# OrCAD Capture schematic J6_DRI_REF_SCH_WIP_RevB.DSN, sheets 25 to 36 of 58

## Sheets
25 SH28 - DDR3 BANK1 CAPS: size B; rev: A
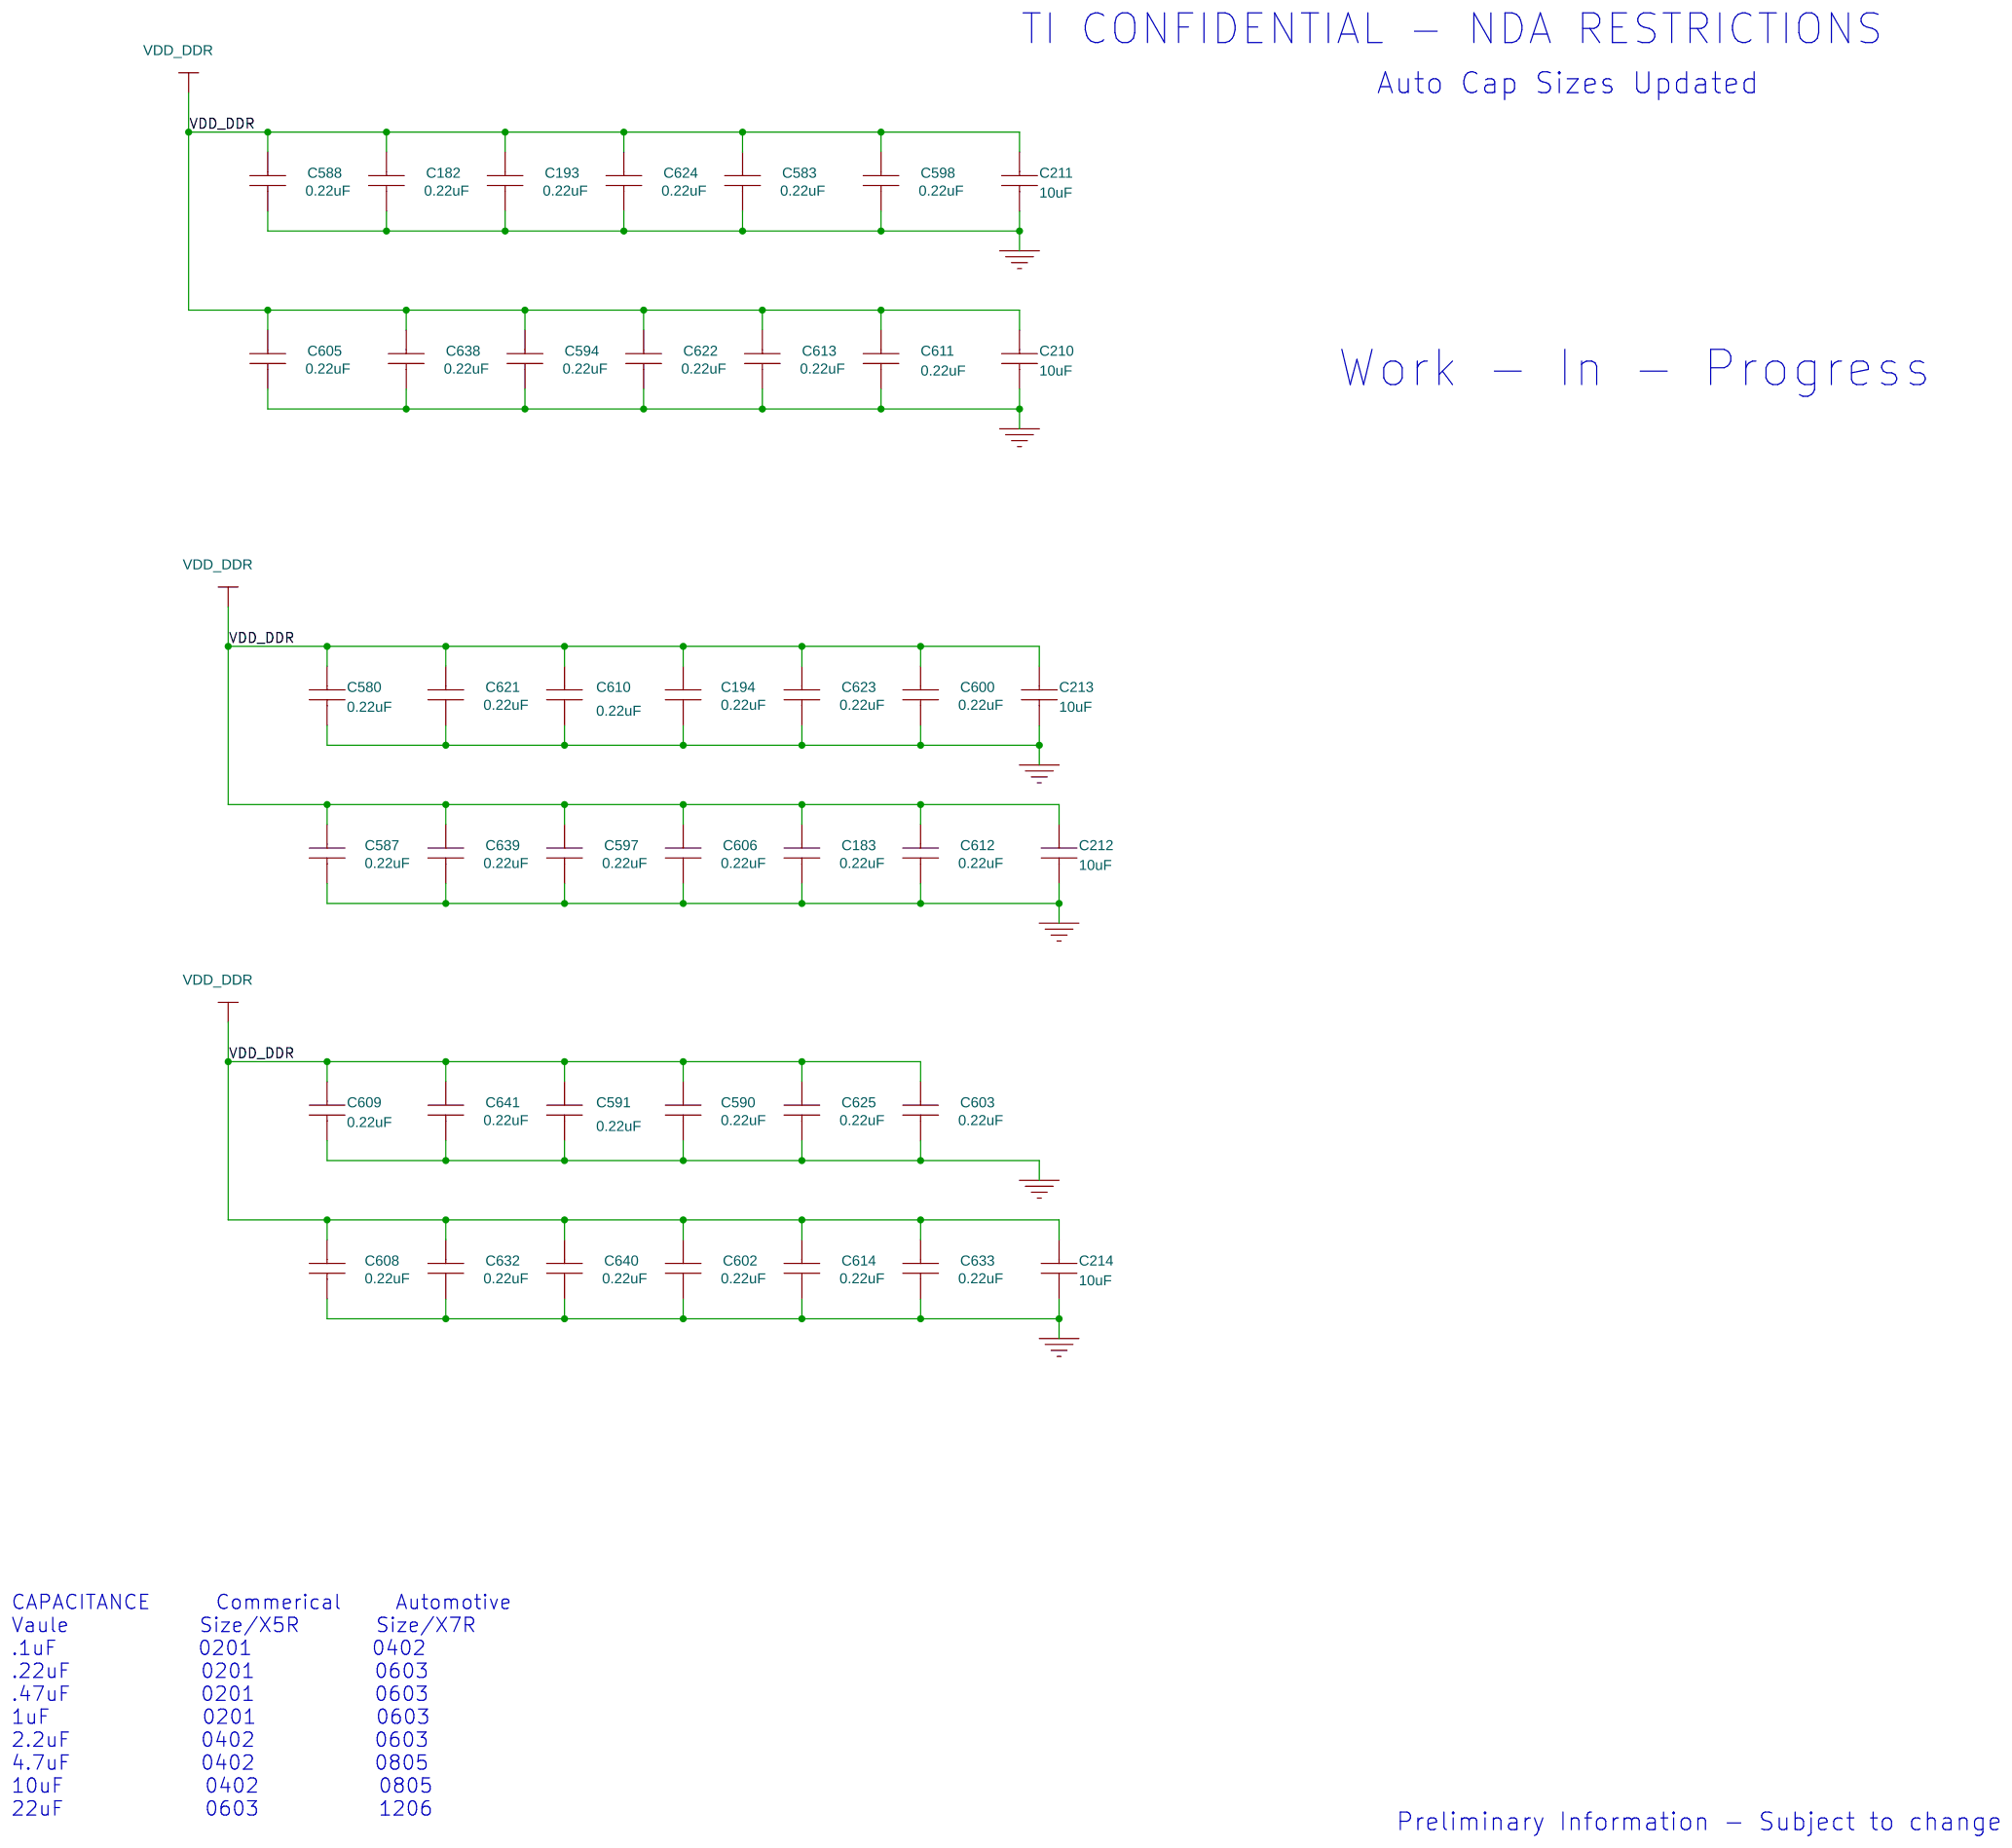
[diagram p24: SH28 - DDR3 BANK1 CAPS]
26 SH29 - DDR3 EMIF1 TERM: size B; rev: A
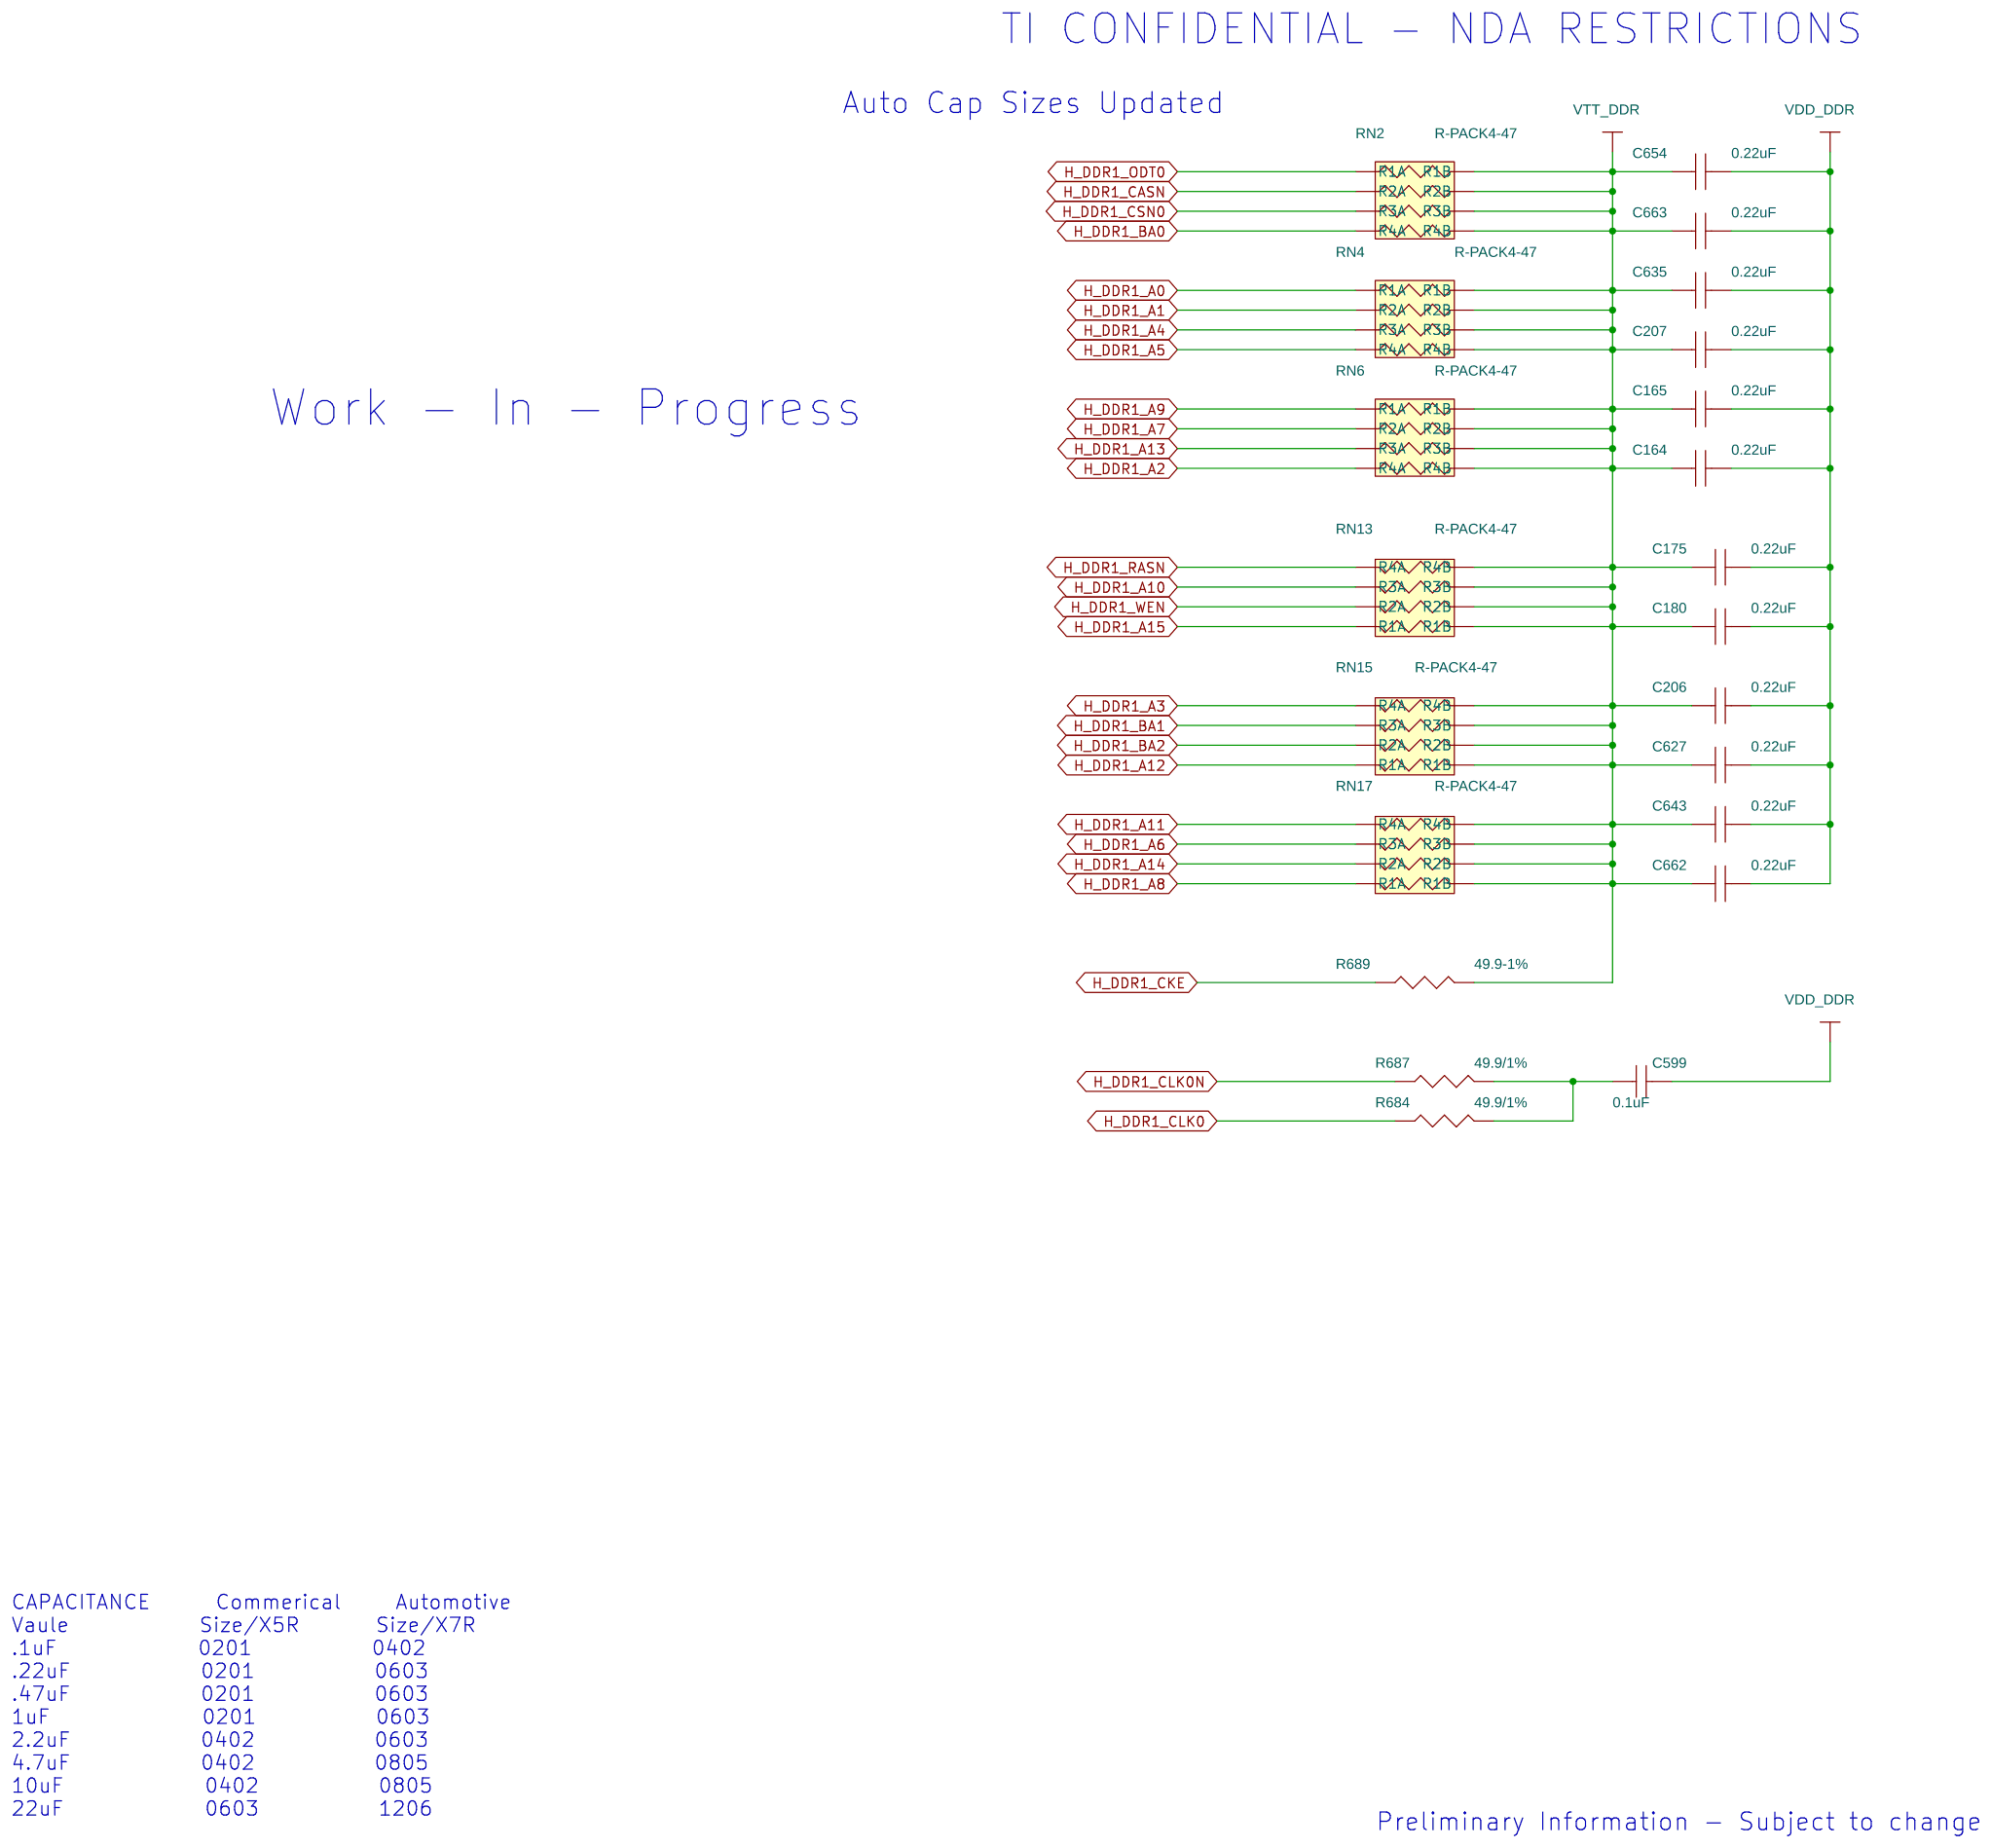
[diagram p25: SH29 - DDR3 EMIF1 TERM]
27 SH30 - DDR3 EMIF2 TESTPOINTS: size B; rev: A
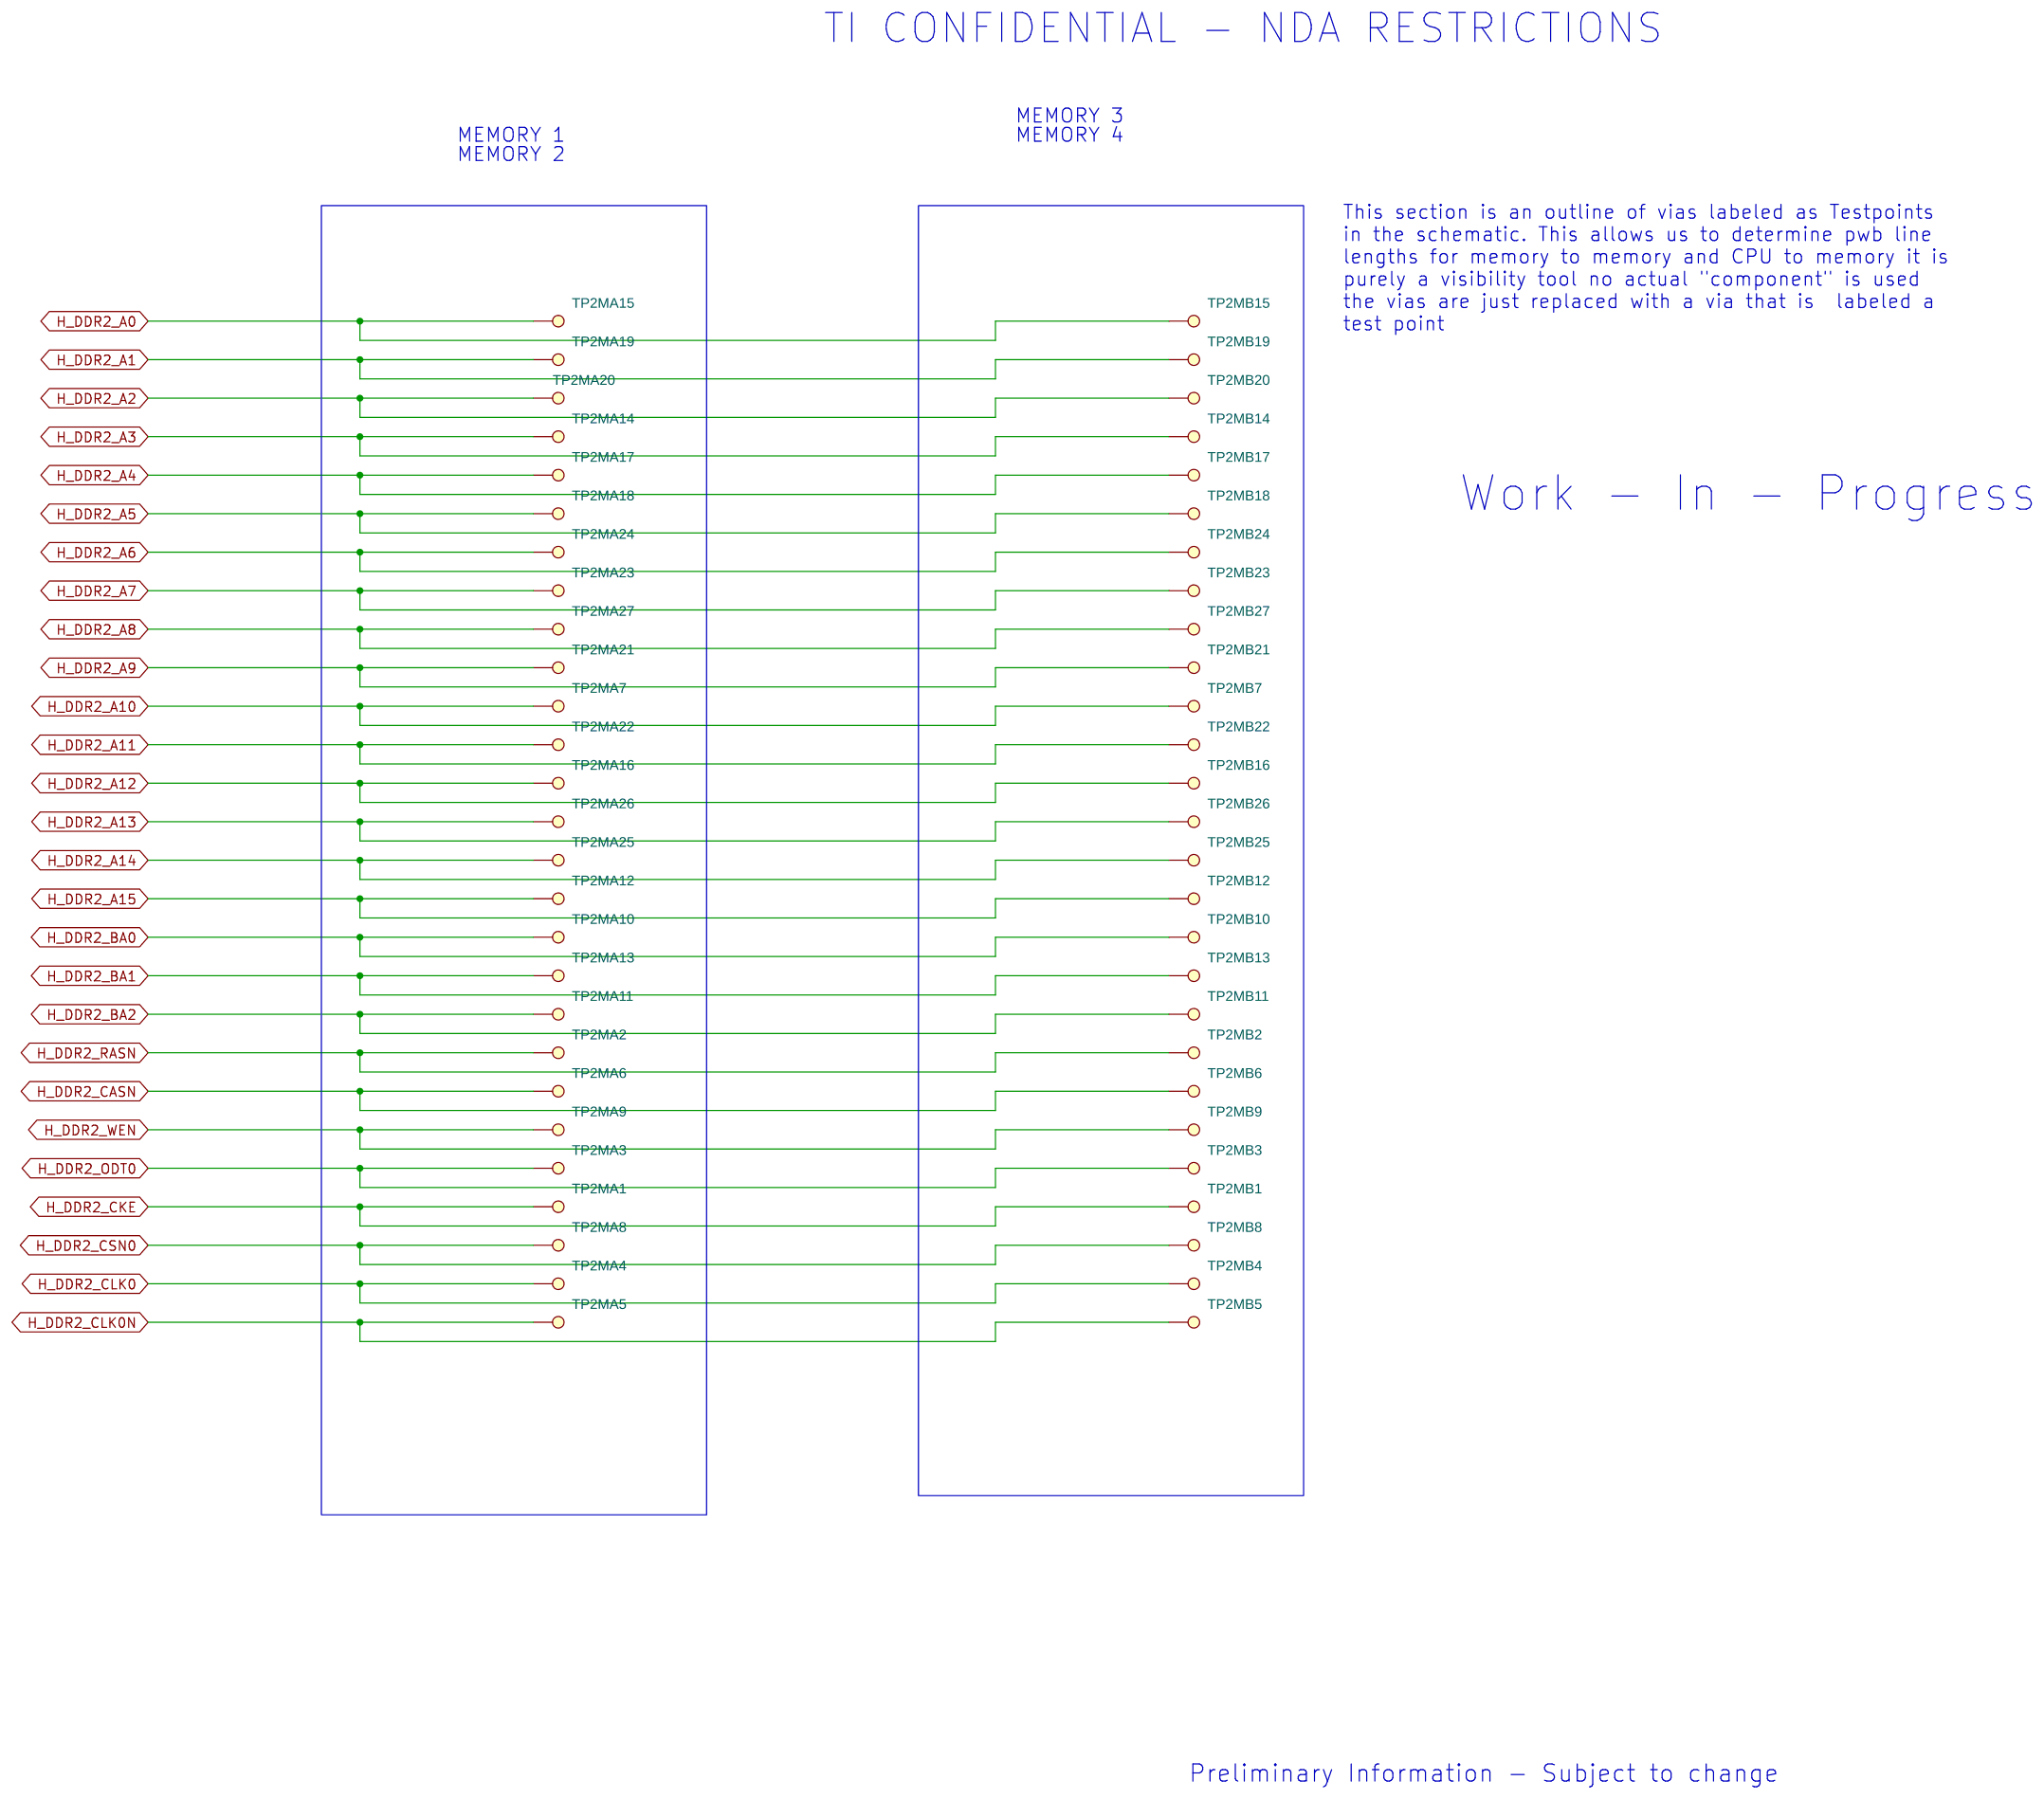
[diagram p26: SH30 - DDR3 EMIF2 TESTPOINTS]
28 SH31 - DDR3 EMIF2 BANK 2: size B; rev: A
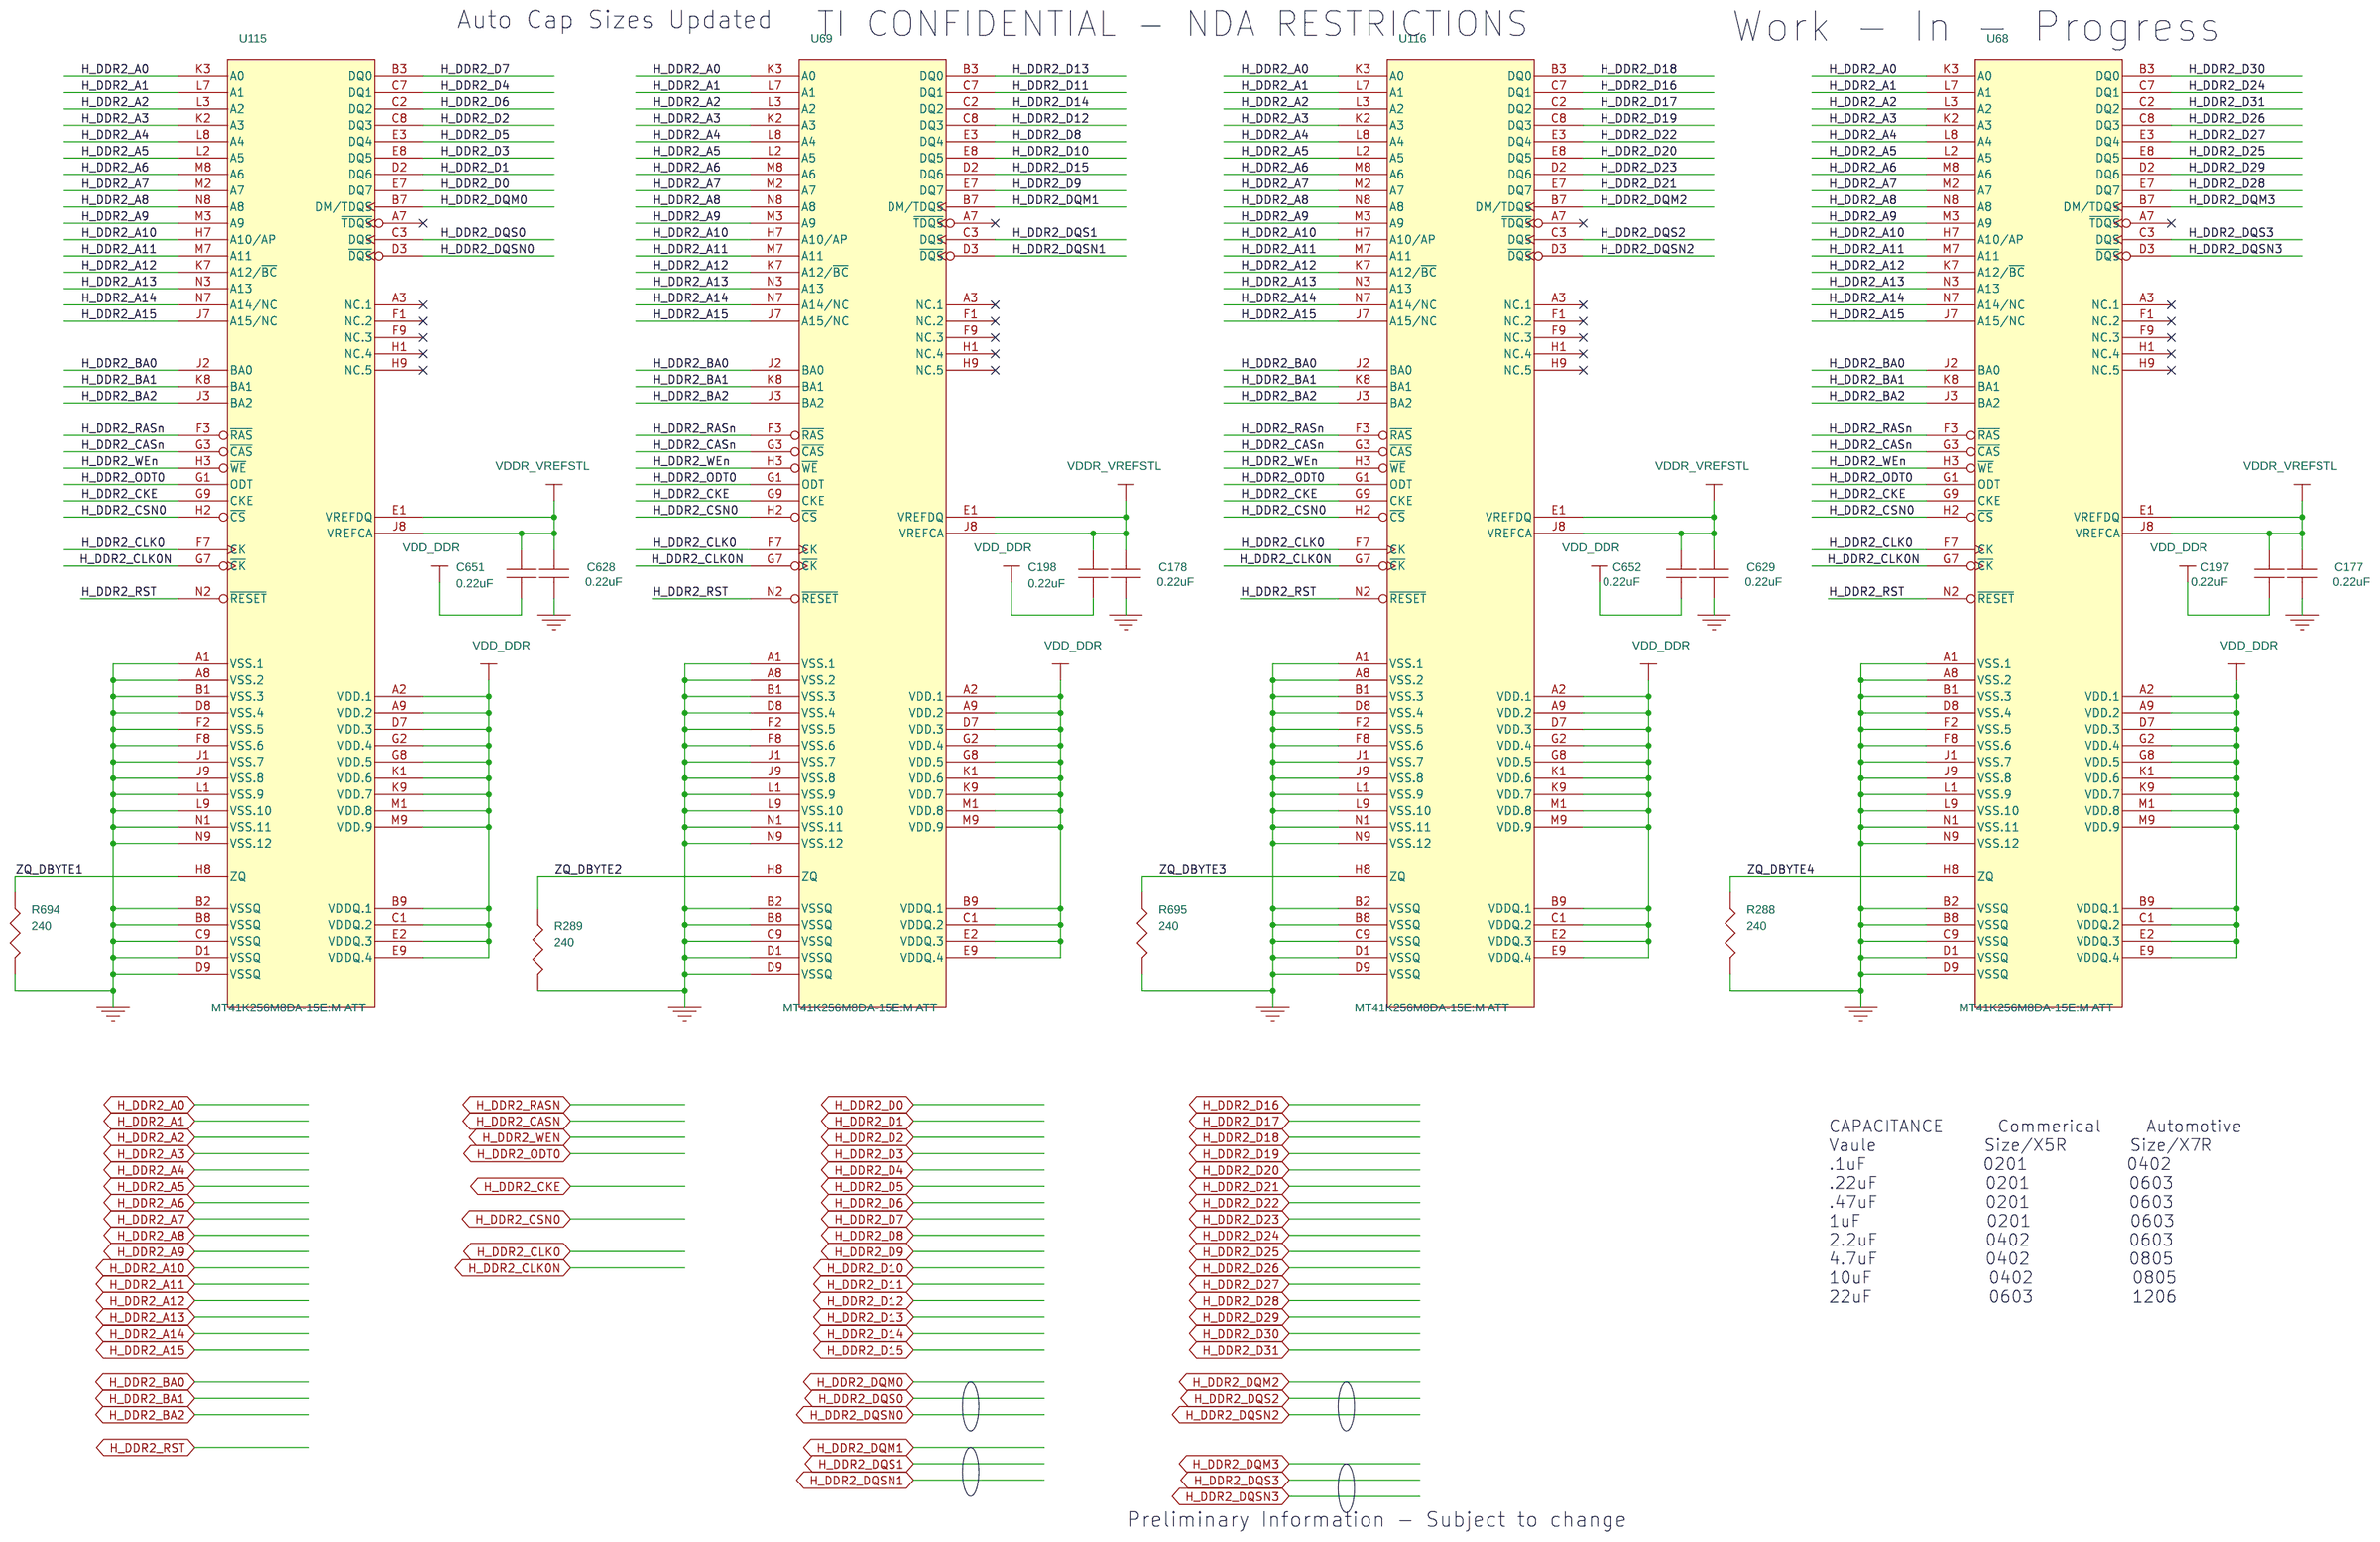
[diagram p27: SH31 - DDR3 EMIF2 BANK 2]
29 SH32 - DDR3 BANK2 CAPS: size B; rev: A
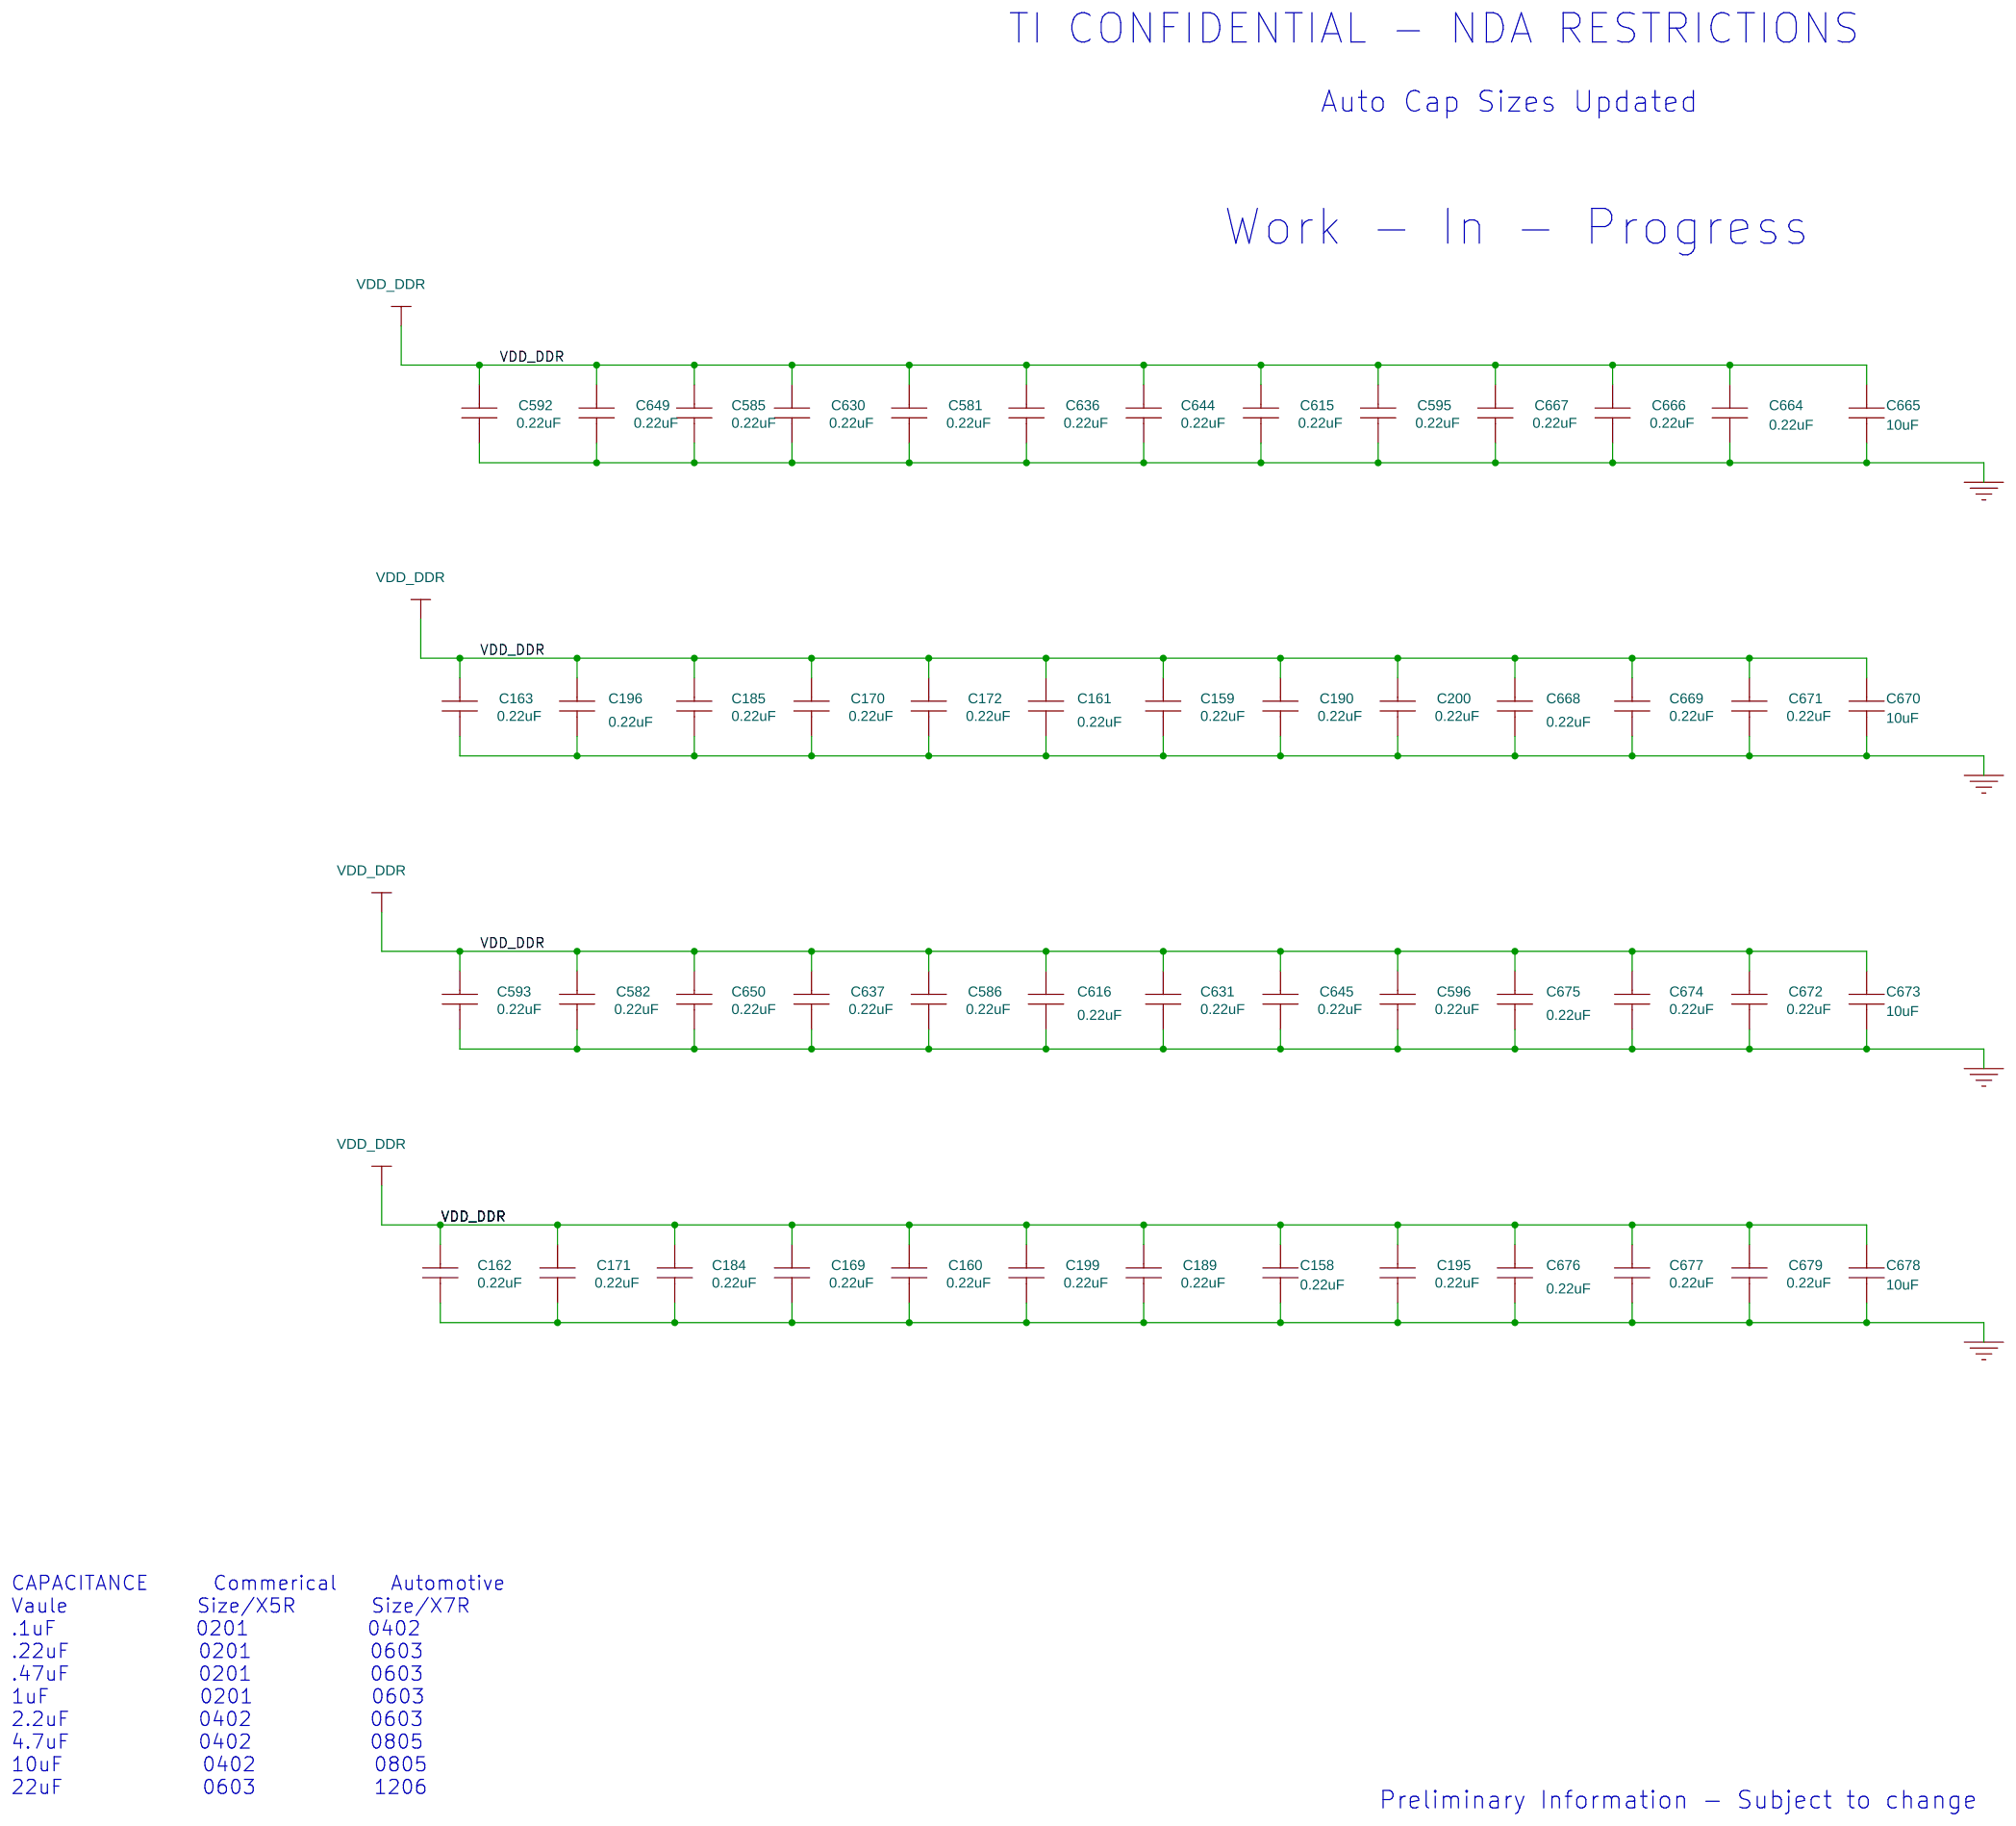
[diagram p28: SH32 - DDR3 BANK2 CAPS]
30 SH33 - DDR3 EMIF2 TERM: size B; rev: A
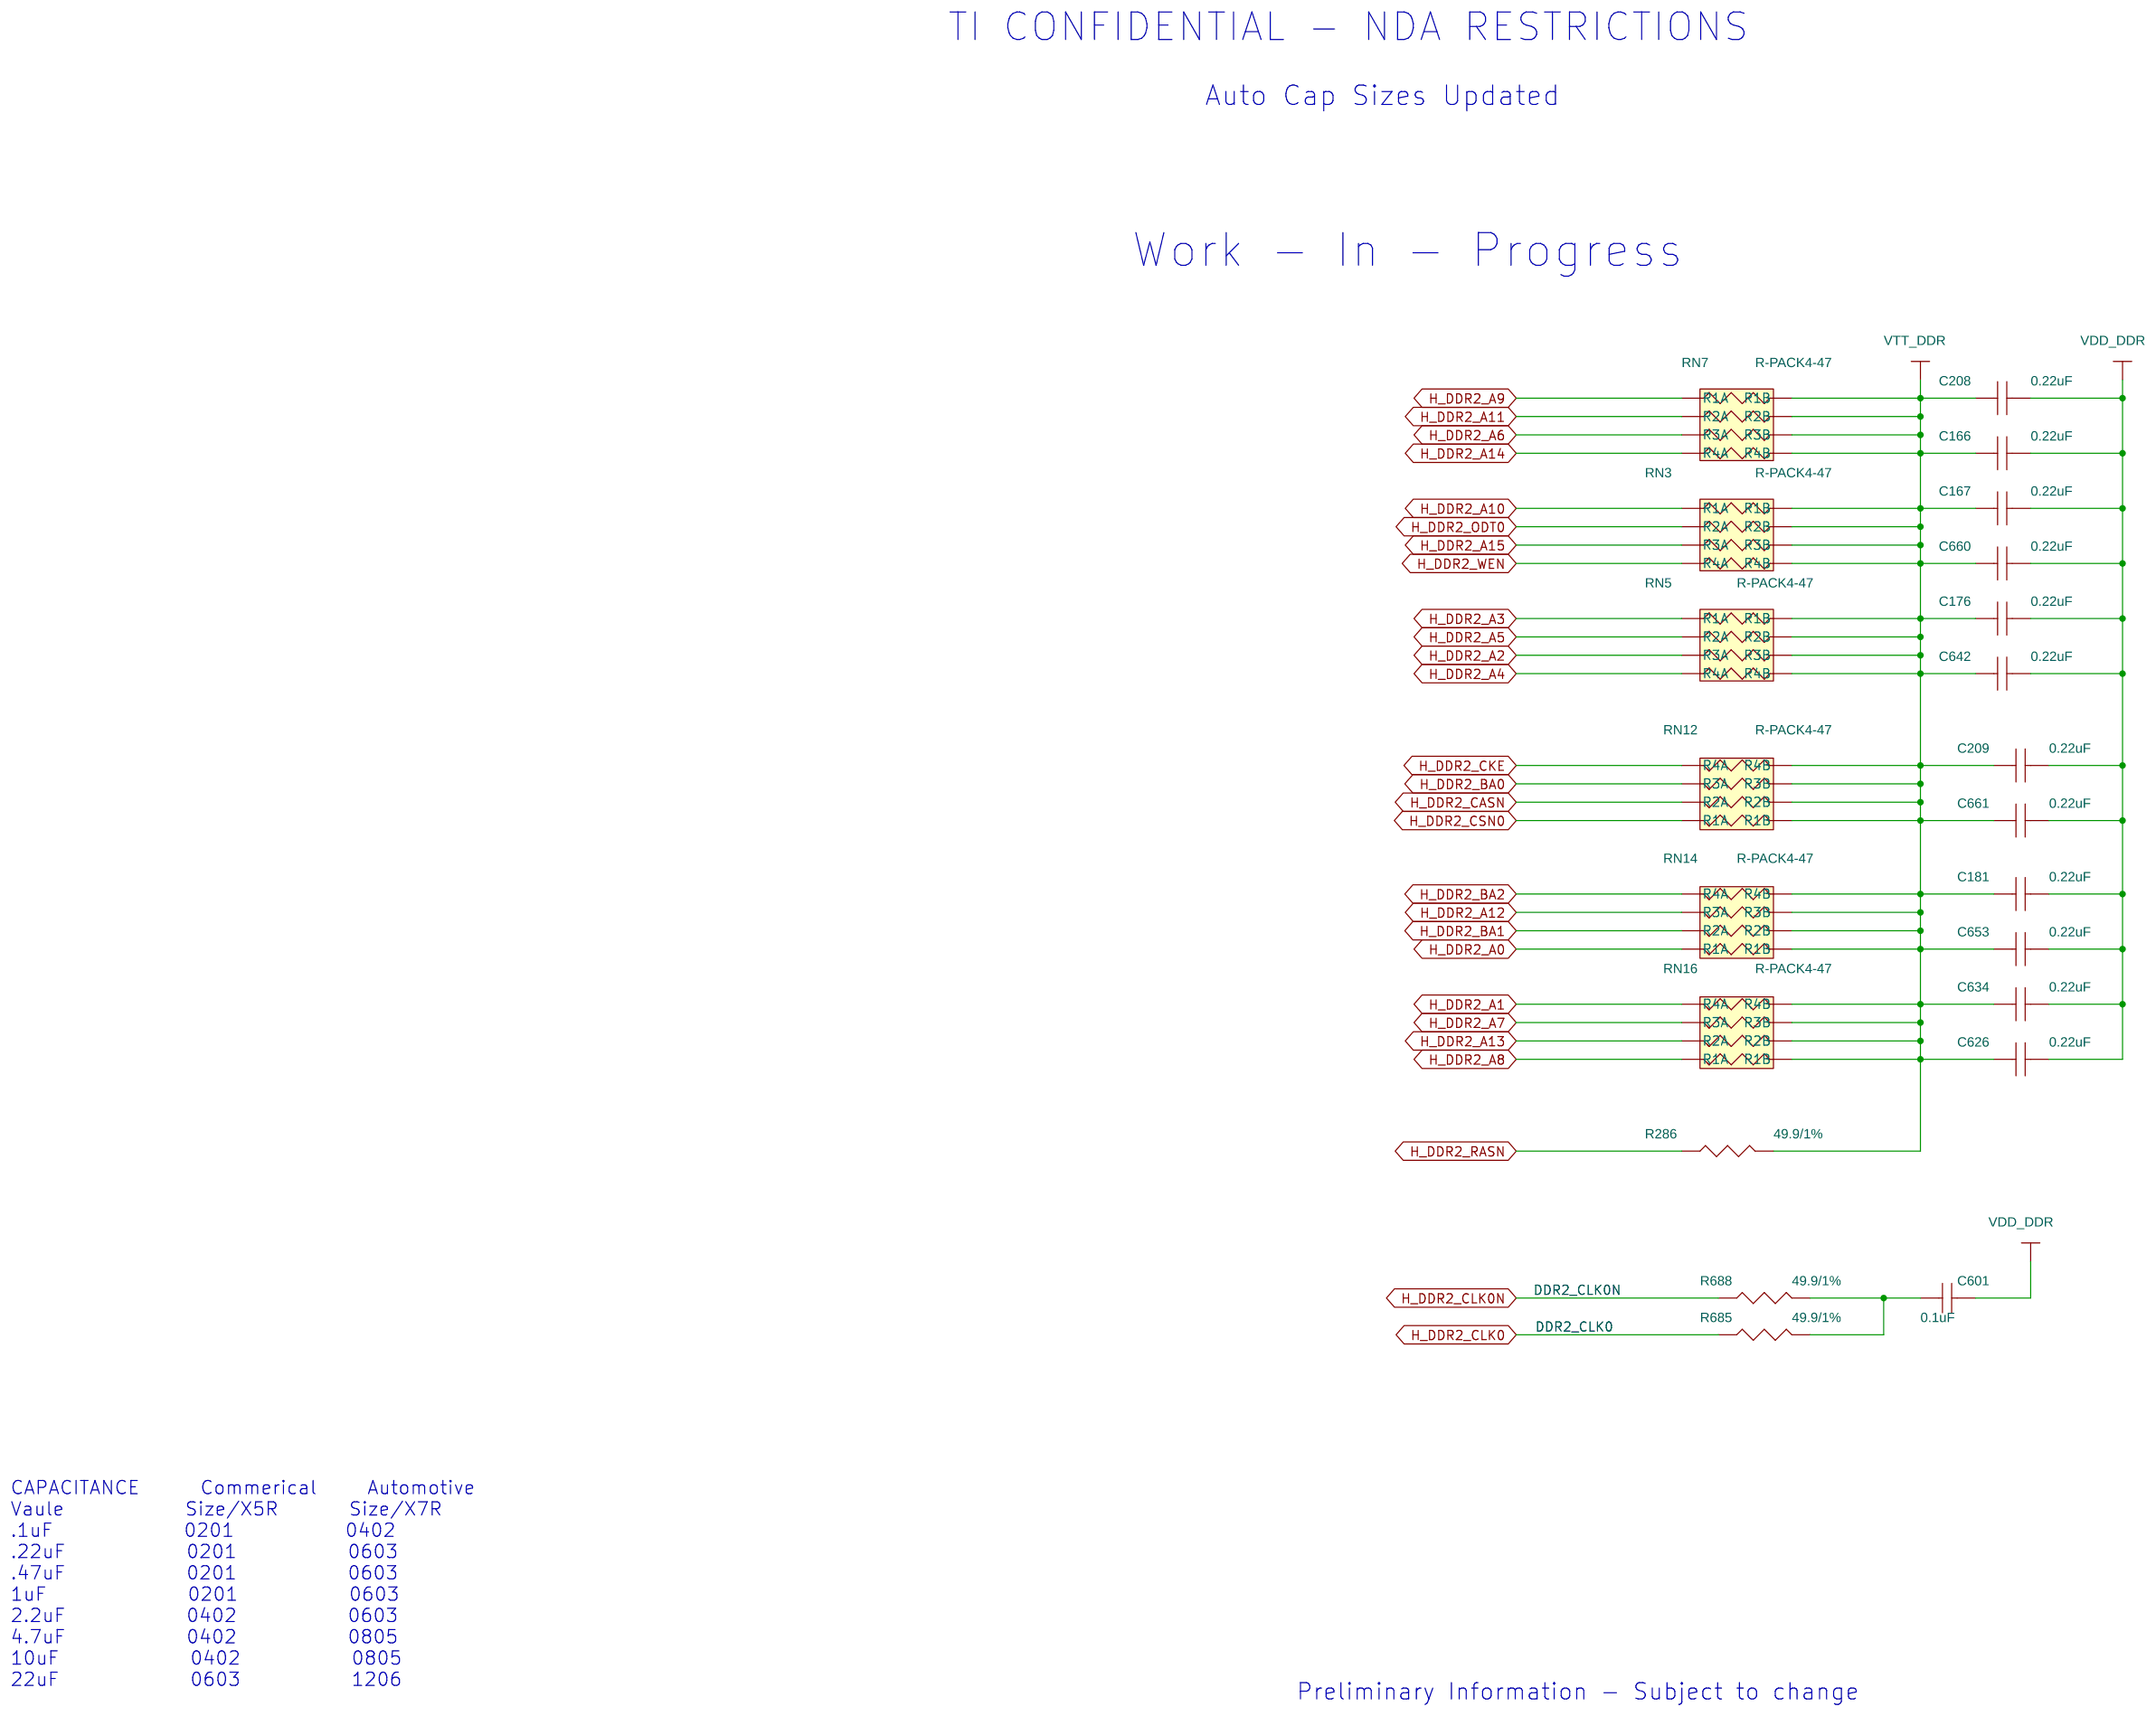
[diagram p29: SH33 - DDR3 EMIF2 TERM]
31 SH33 - HDMI OUTPUT CONNECTOR: size B; title: VAYU EVM; rev: E; note: 516582-0001
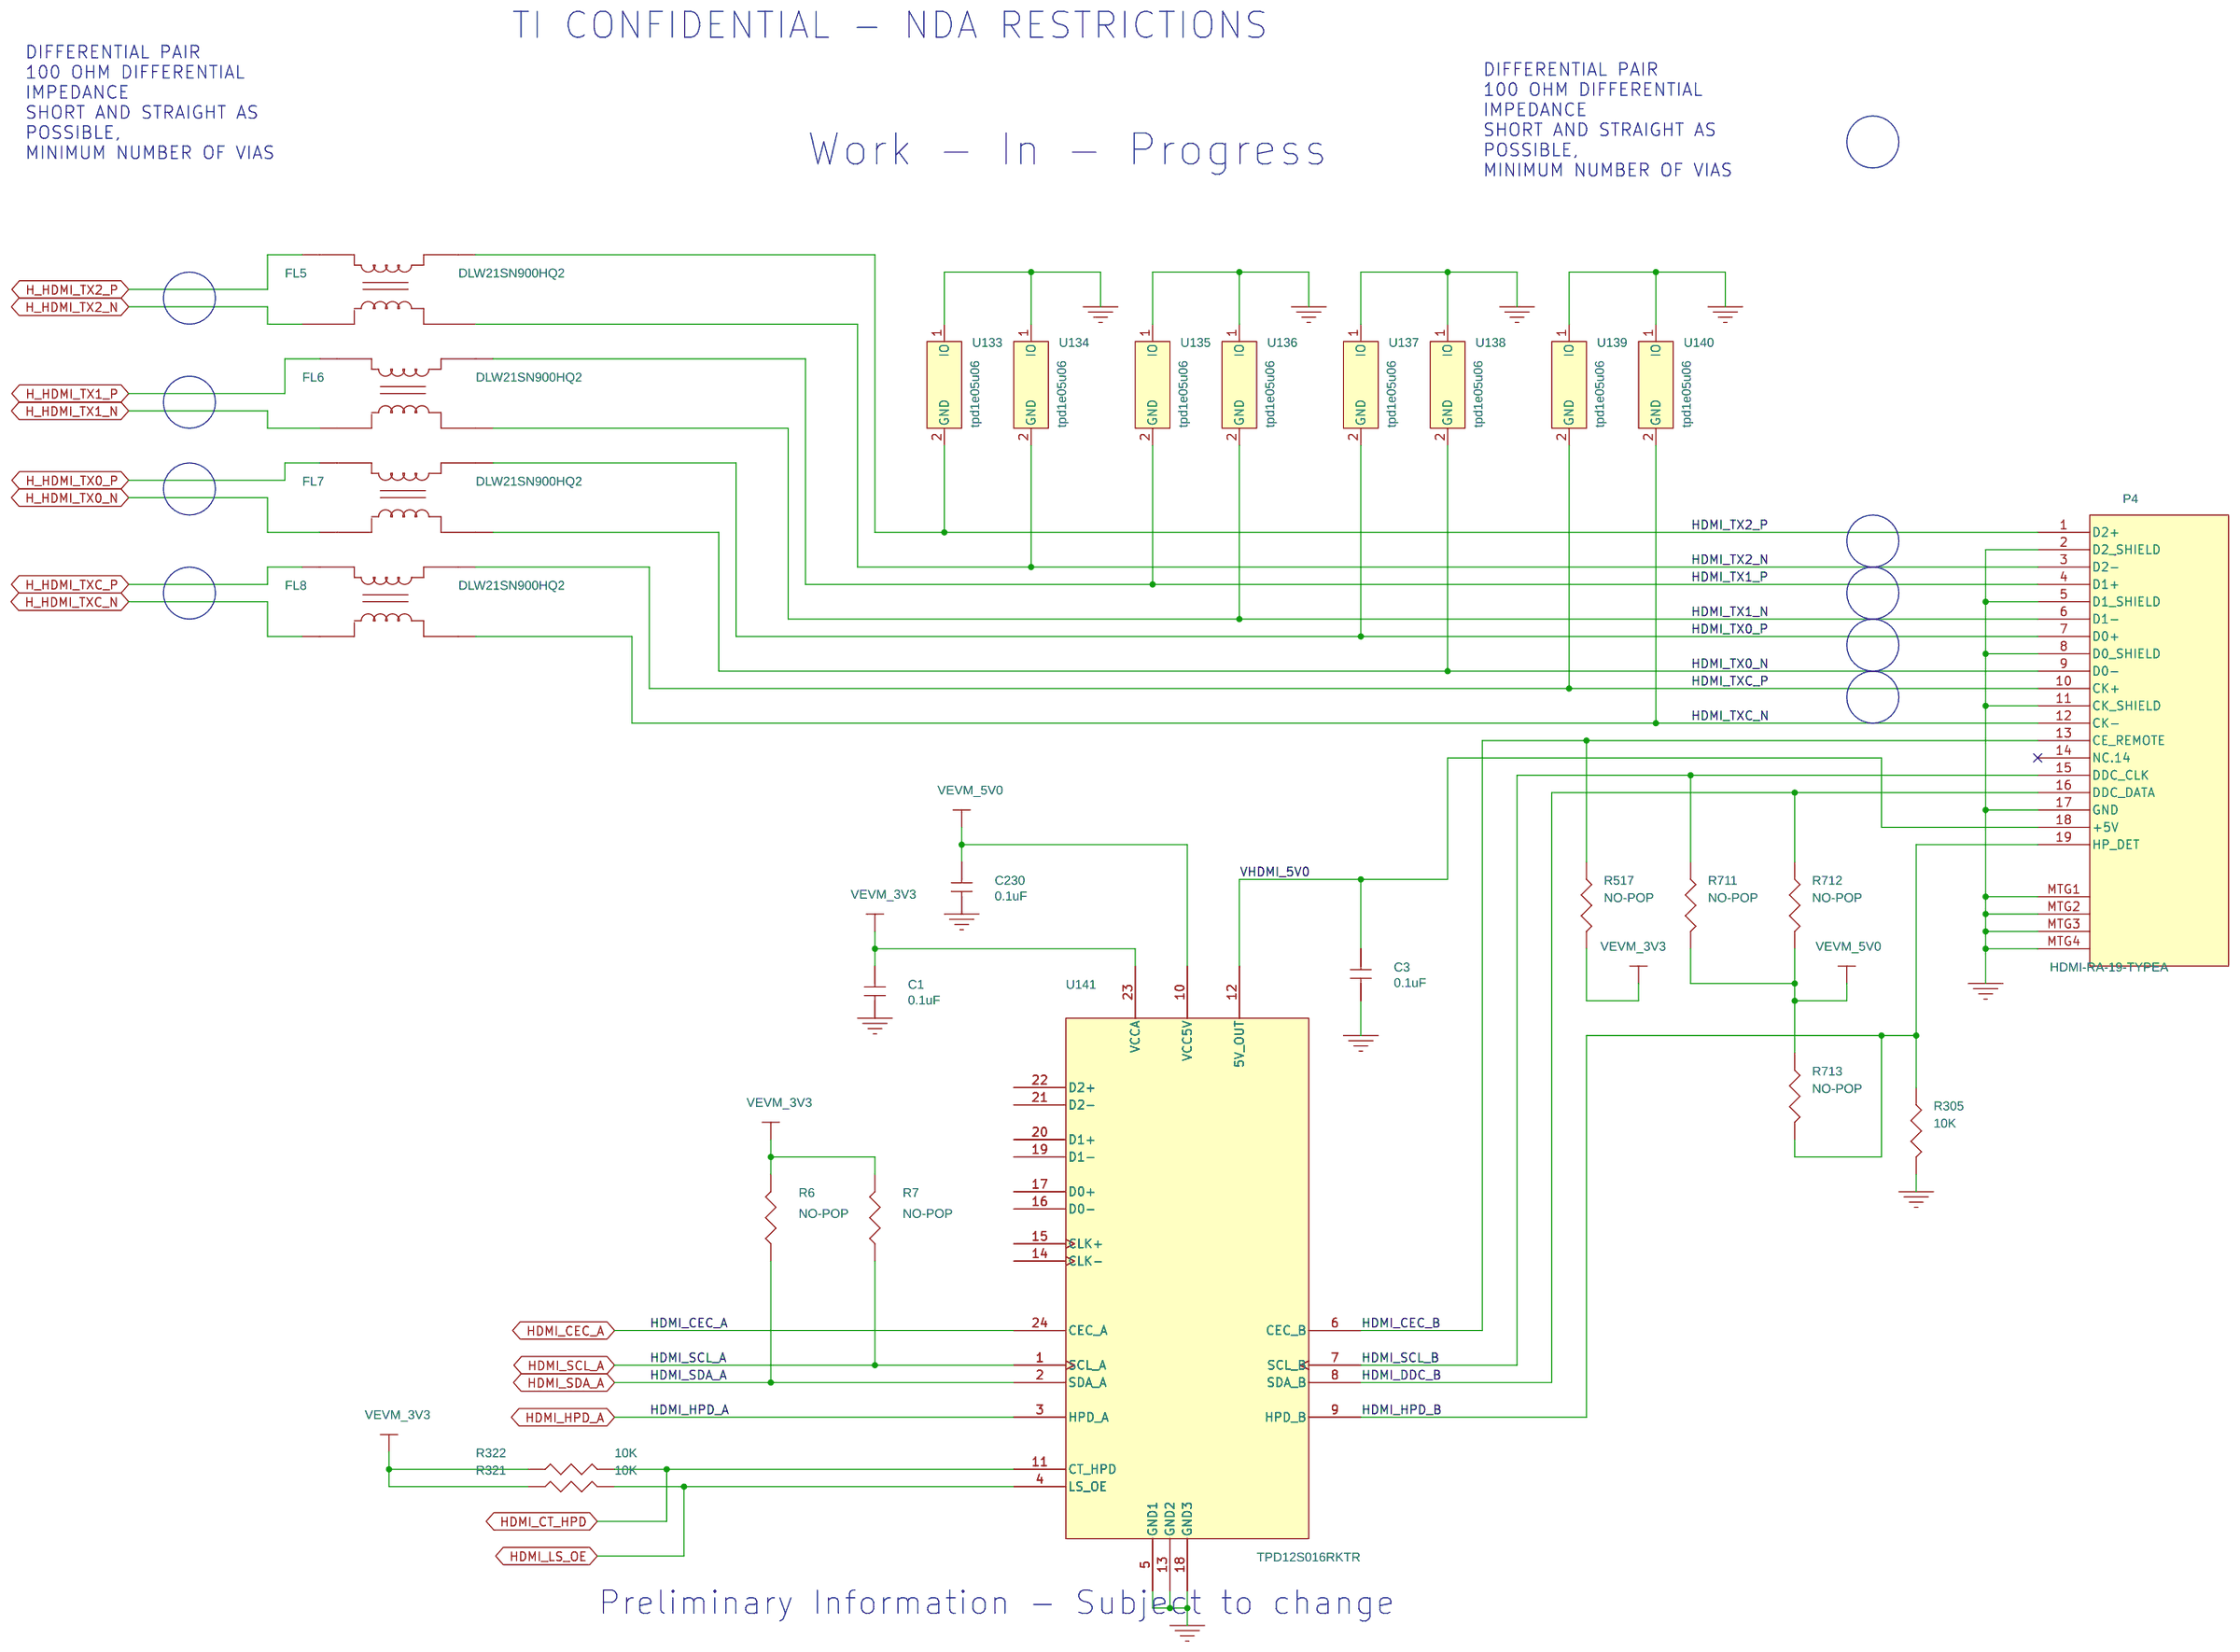
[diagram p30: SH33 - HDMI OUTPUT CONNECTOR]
32 SH34 - USB1: size B; rev: A
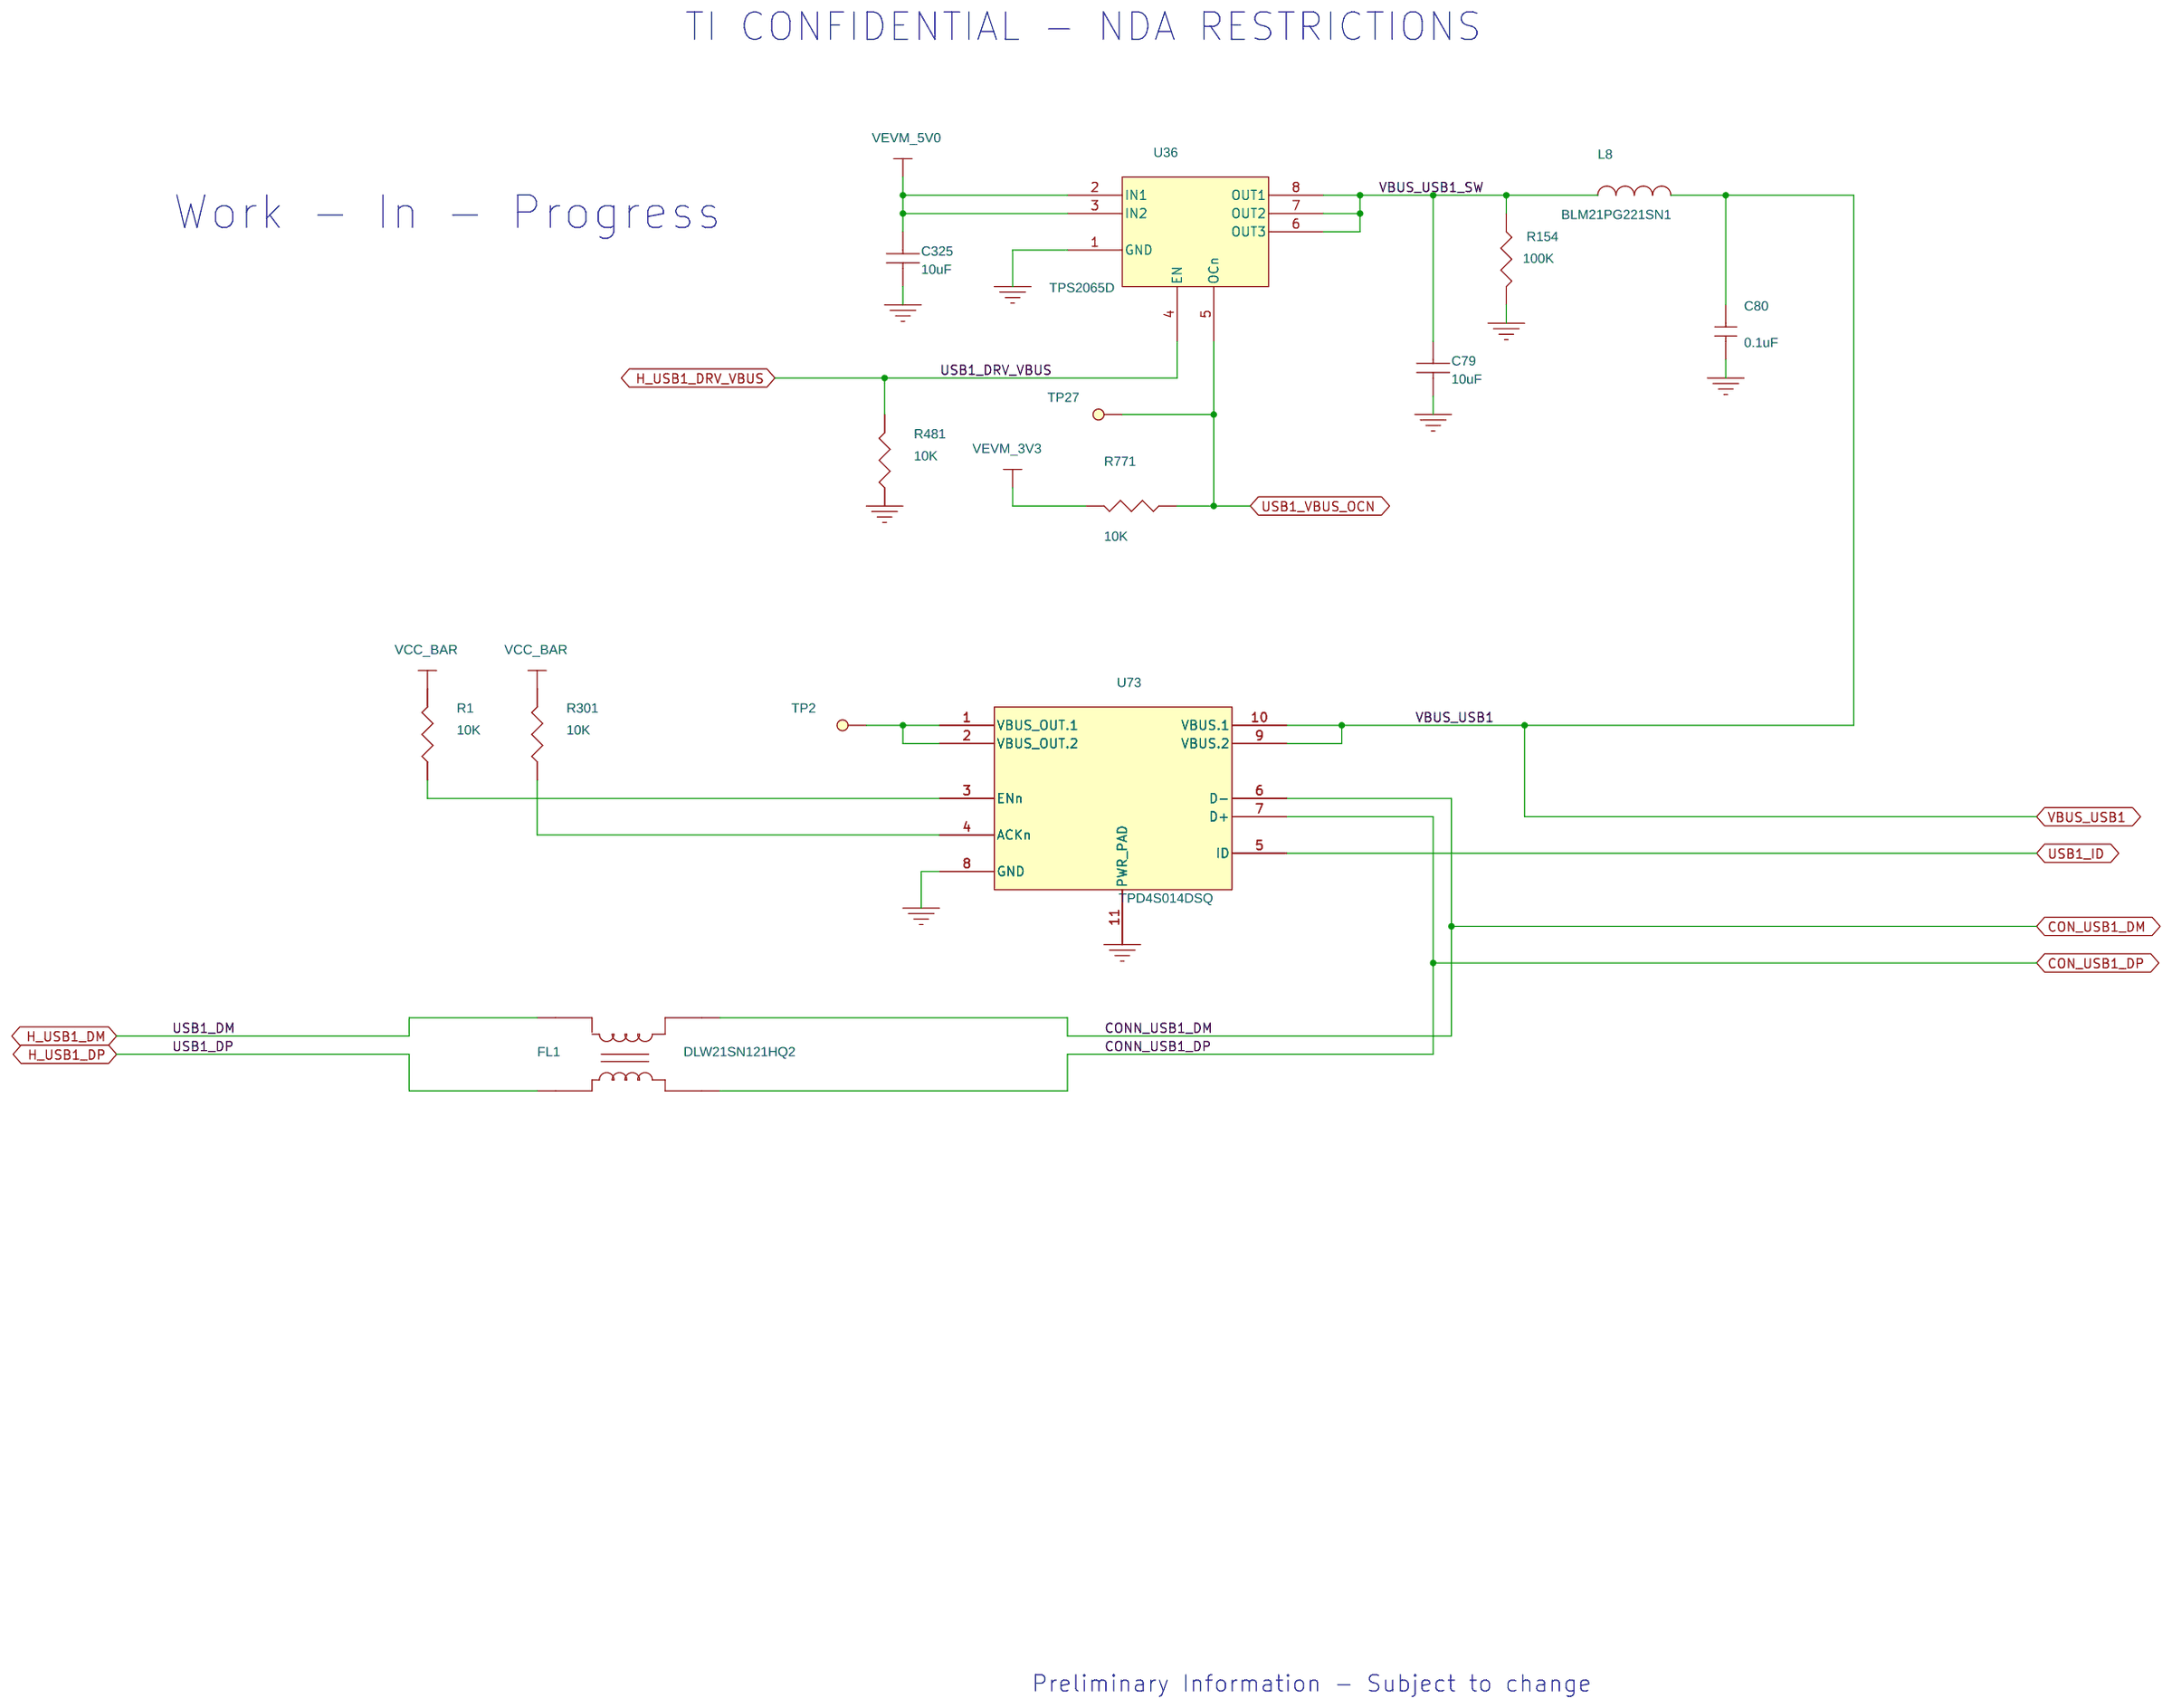
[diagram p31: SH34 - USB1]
33 SH35 - USB2: size B; rev: A
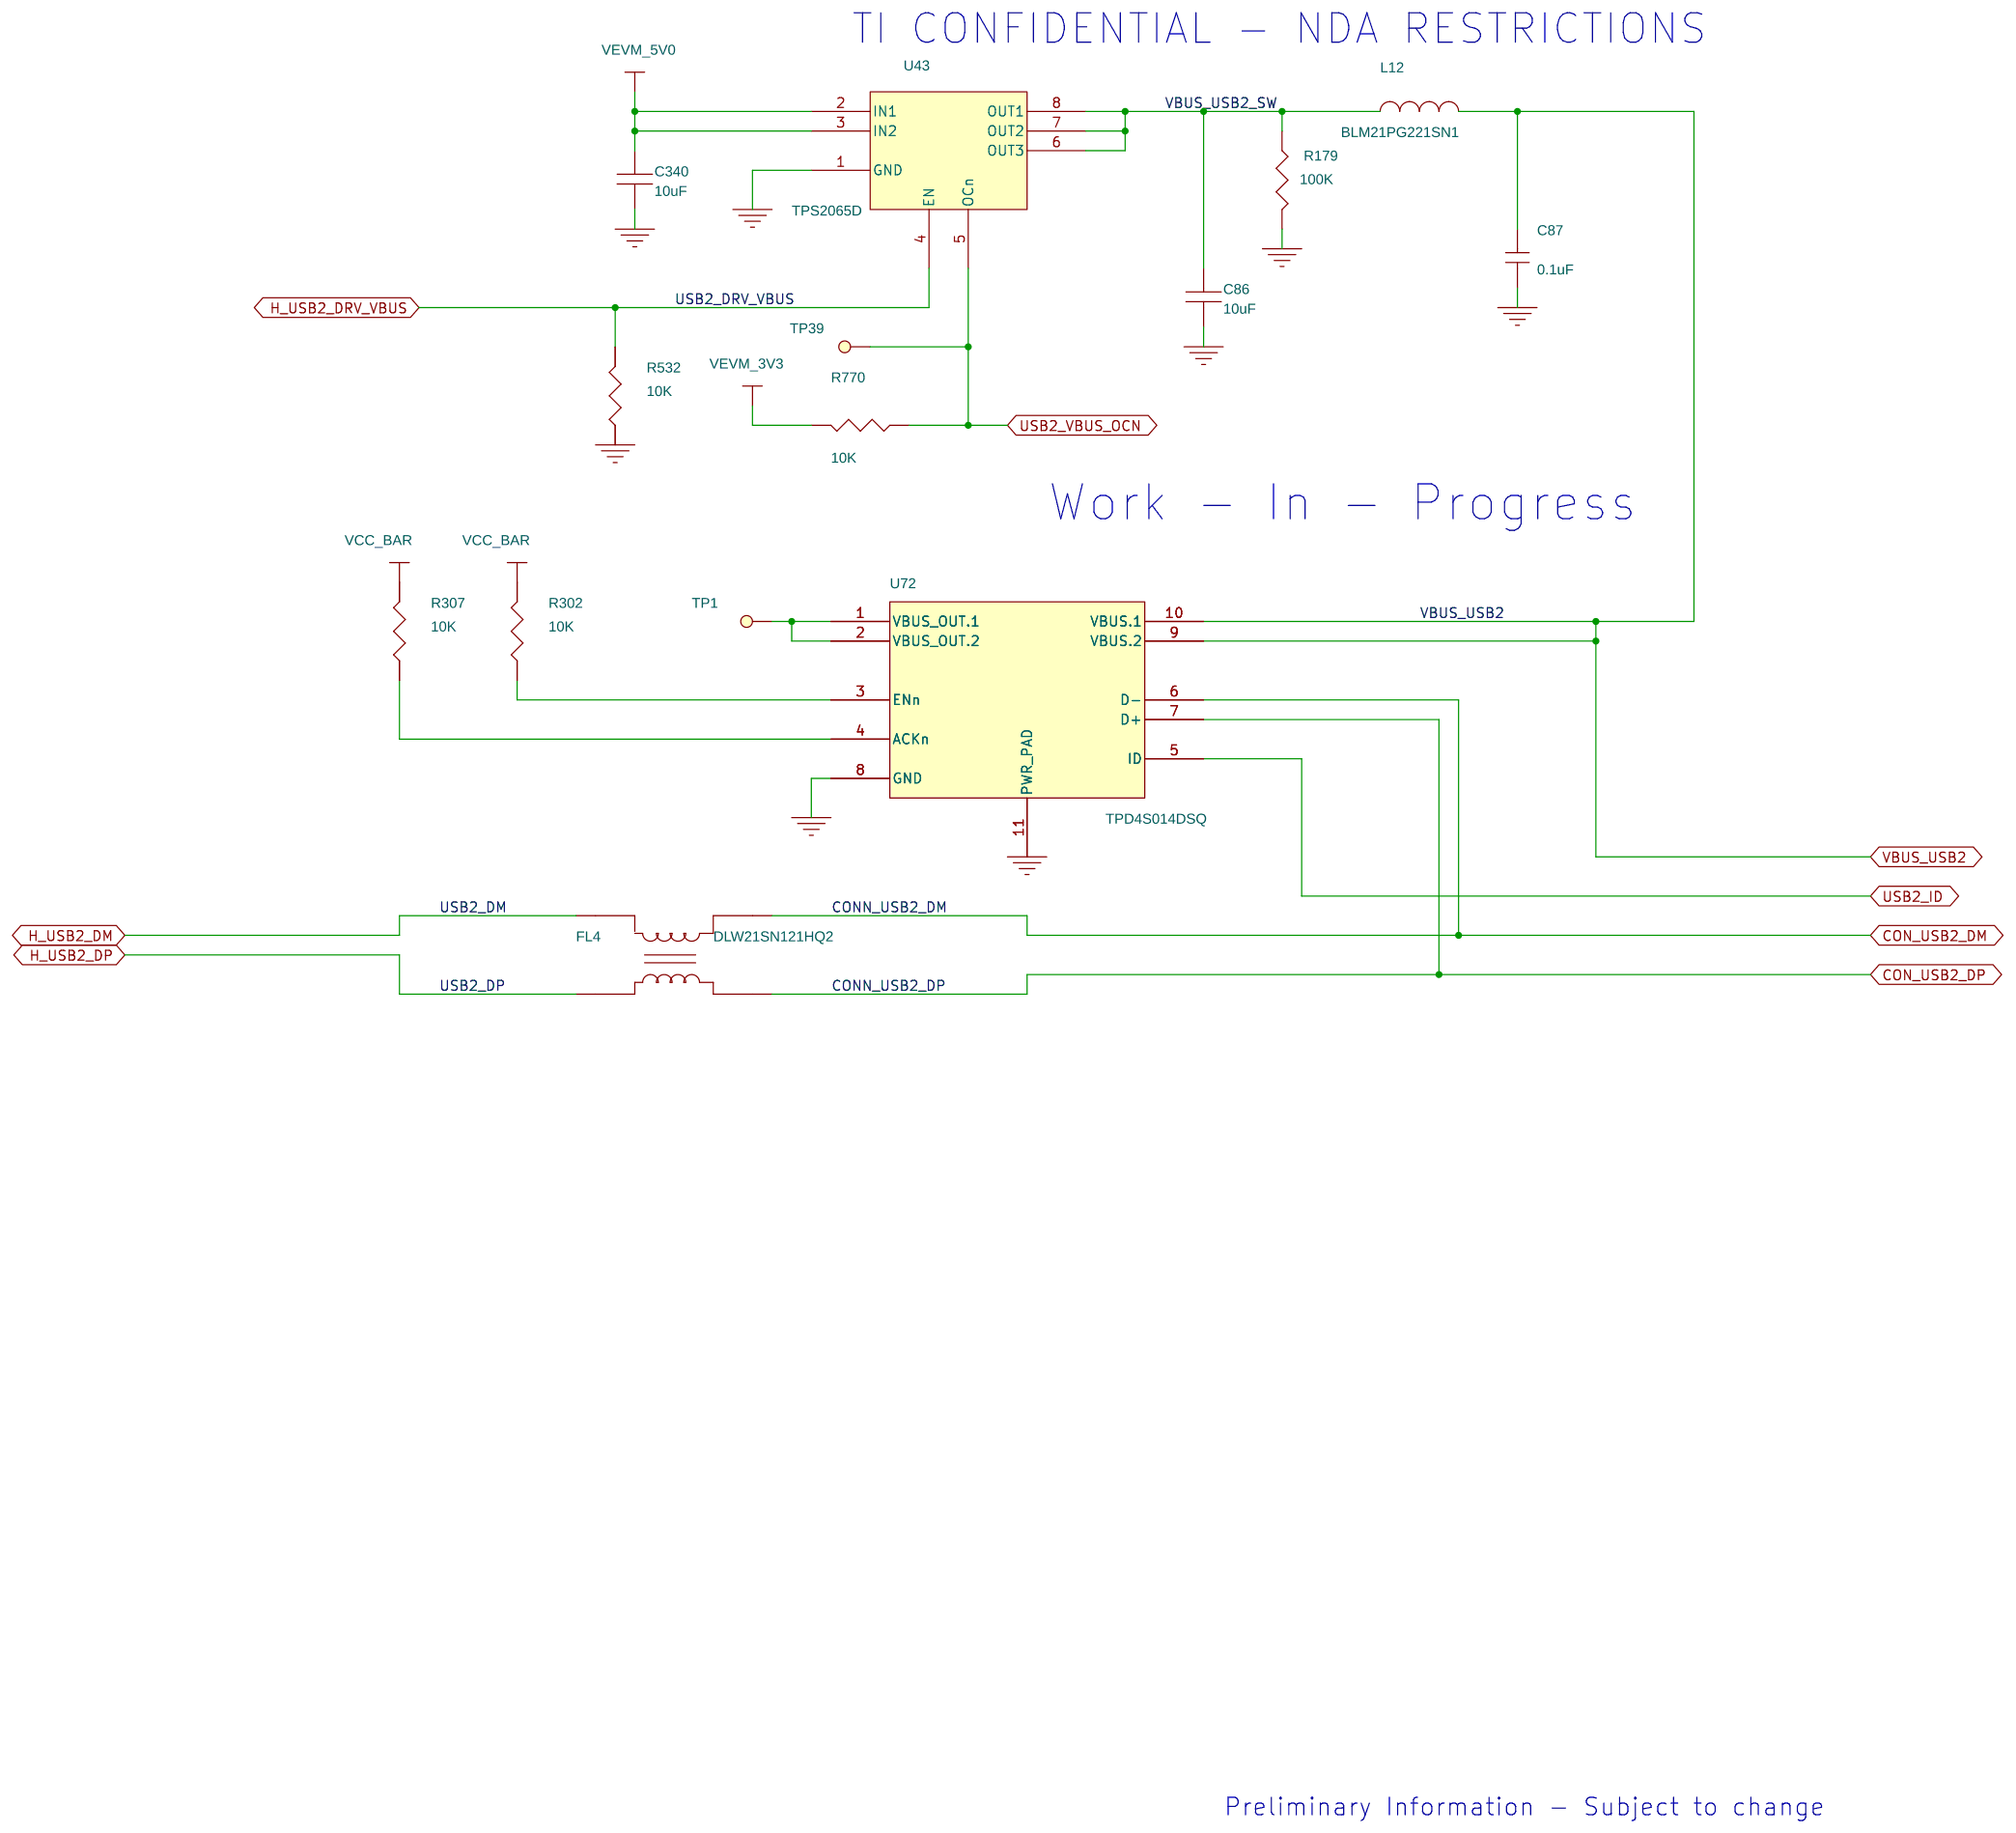
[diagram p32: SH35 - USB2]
34 SH36 - COM8 LEVEL TRANSLATORS: size B; rev: A
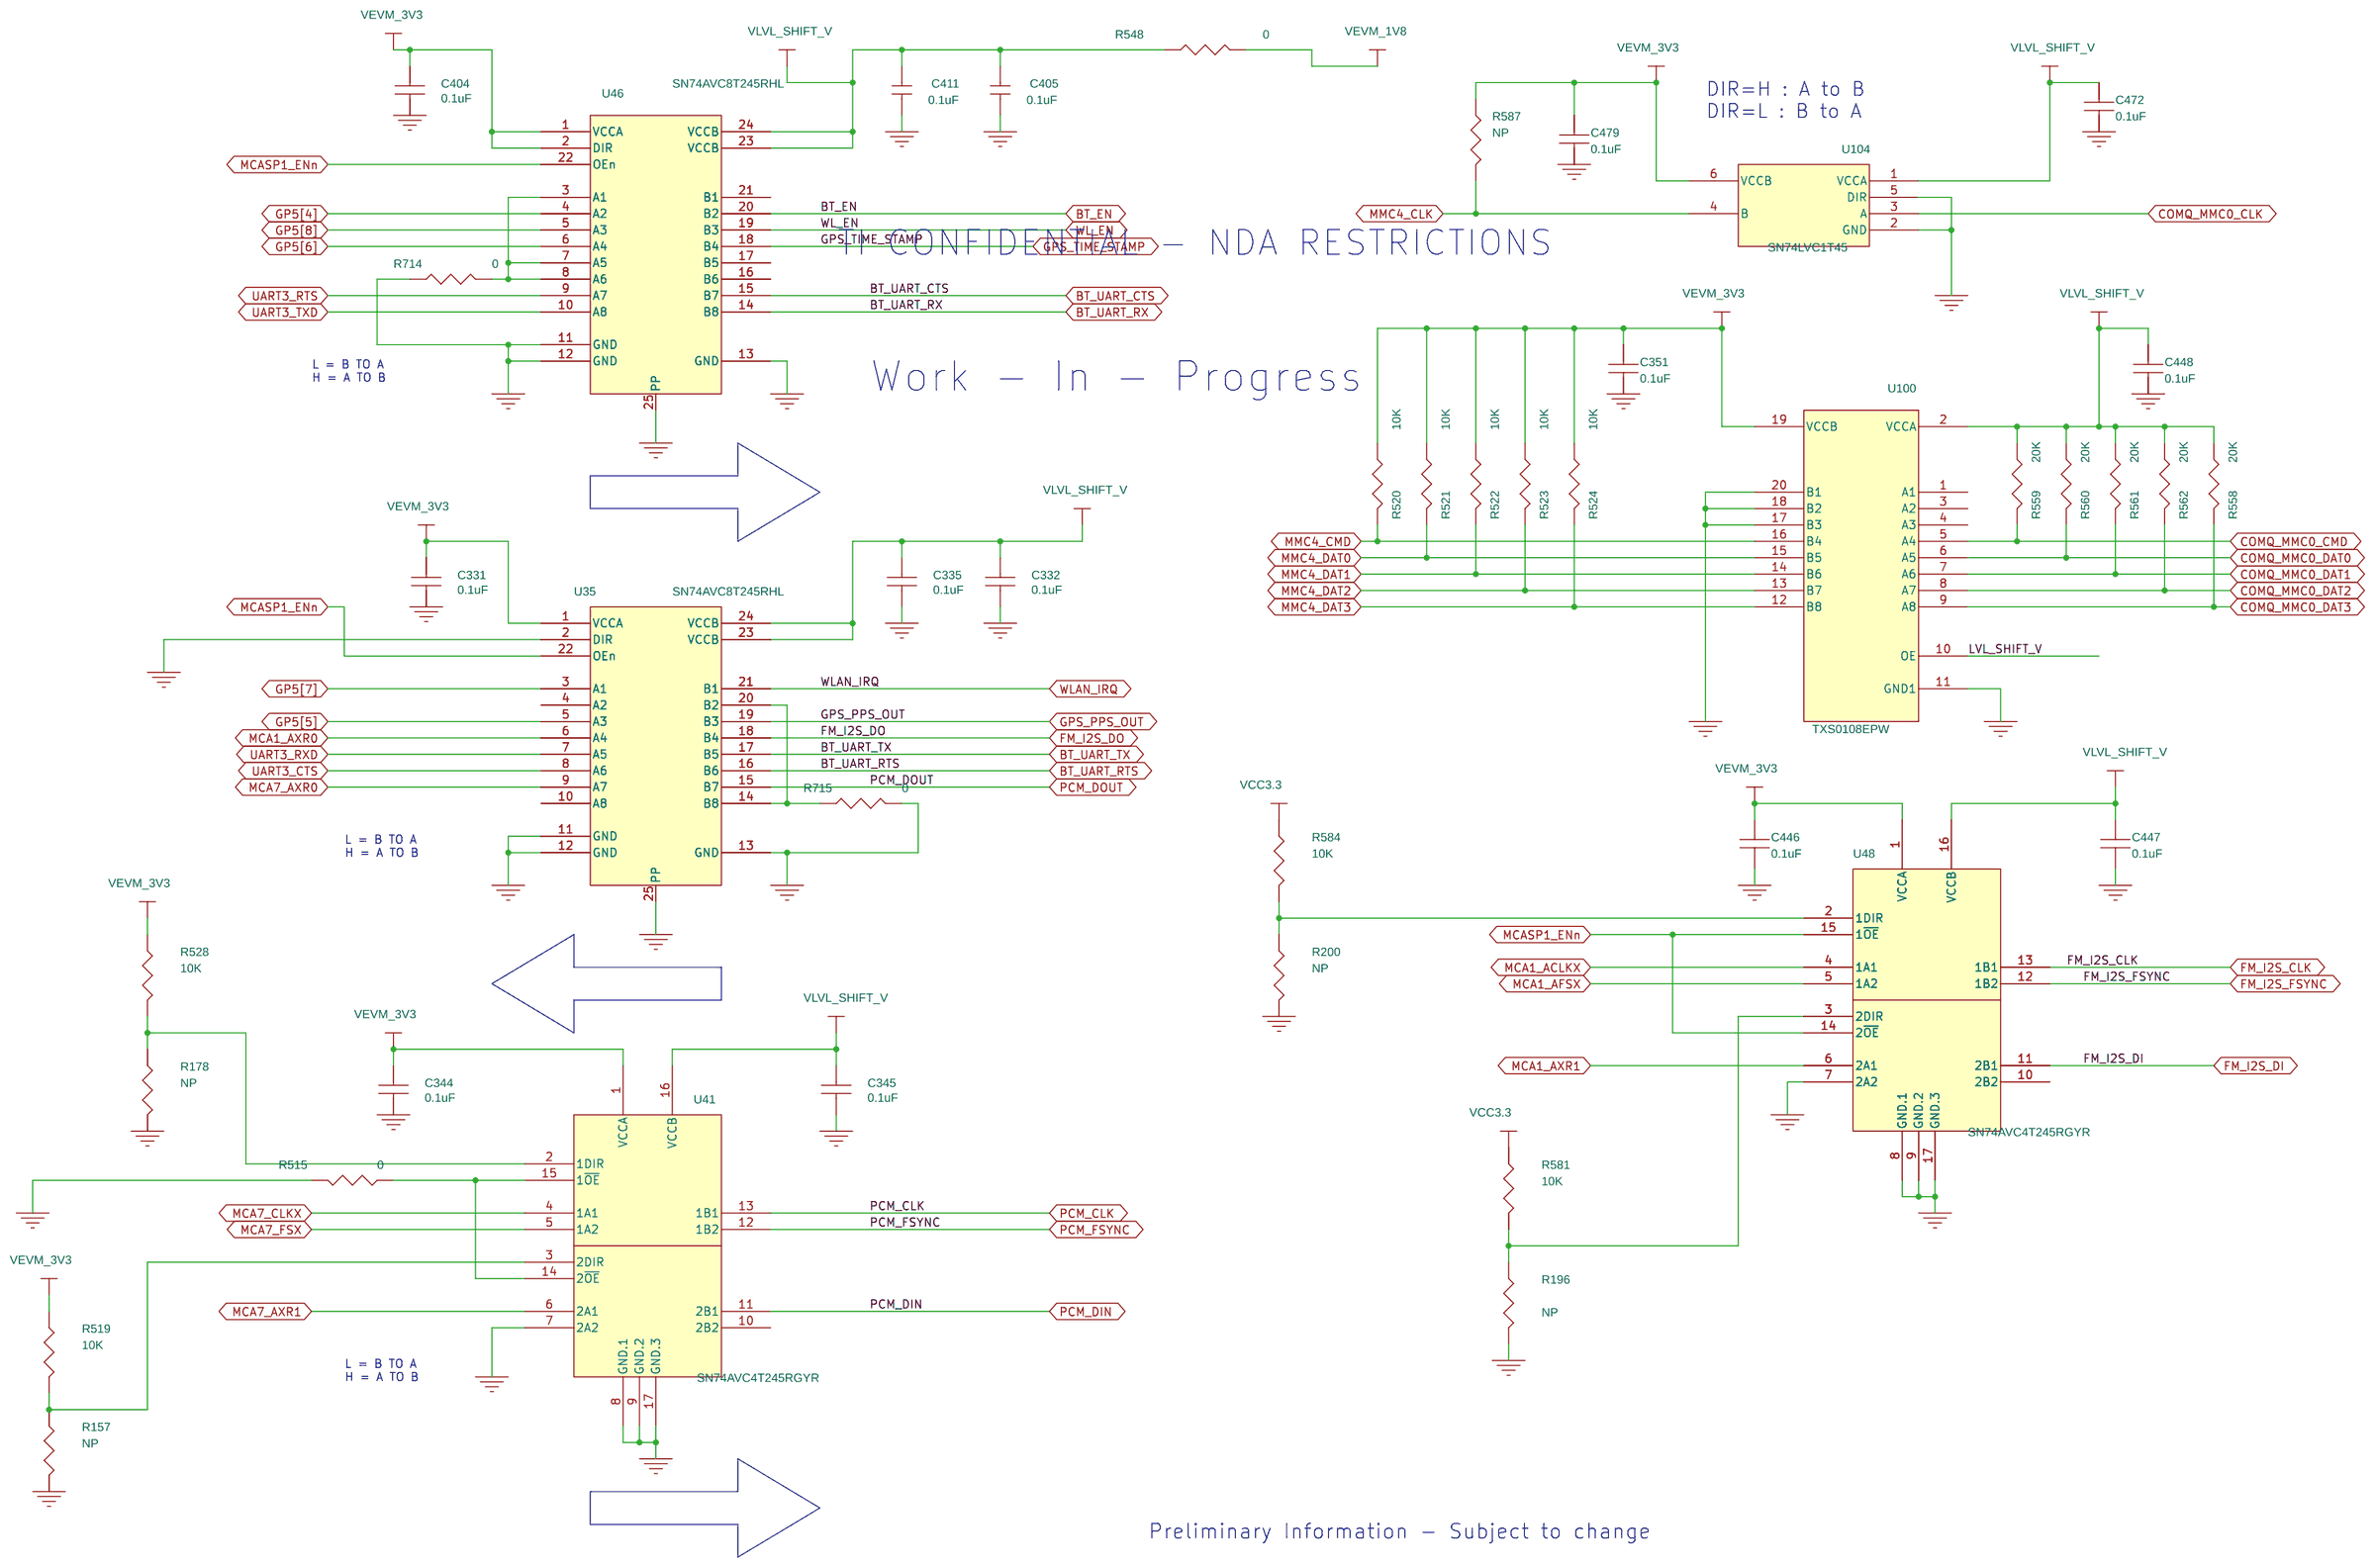
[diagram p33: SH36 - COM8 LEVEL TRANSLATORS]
35 SH37 - COM8 CONNECTOR: size B; rev: A
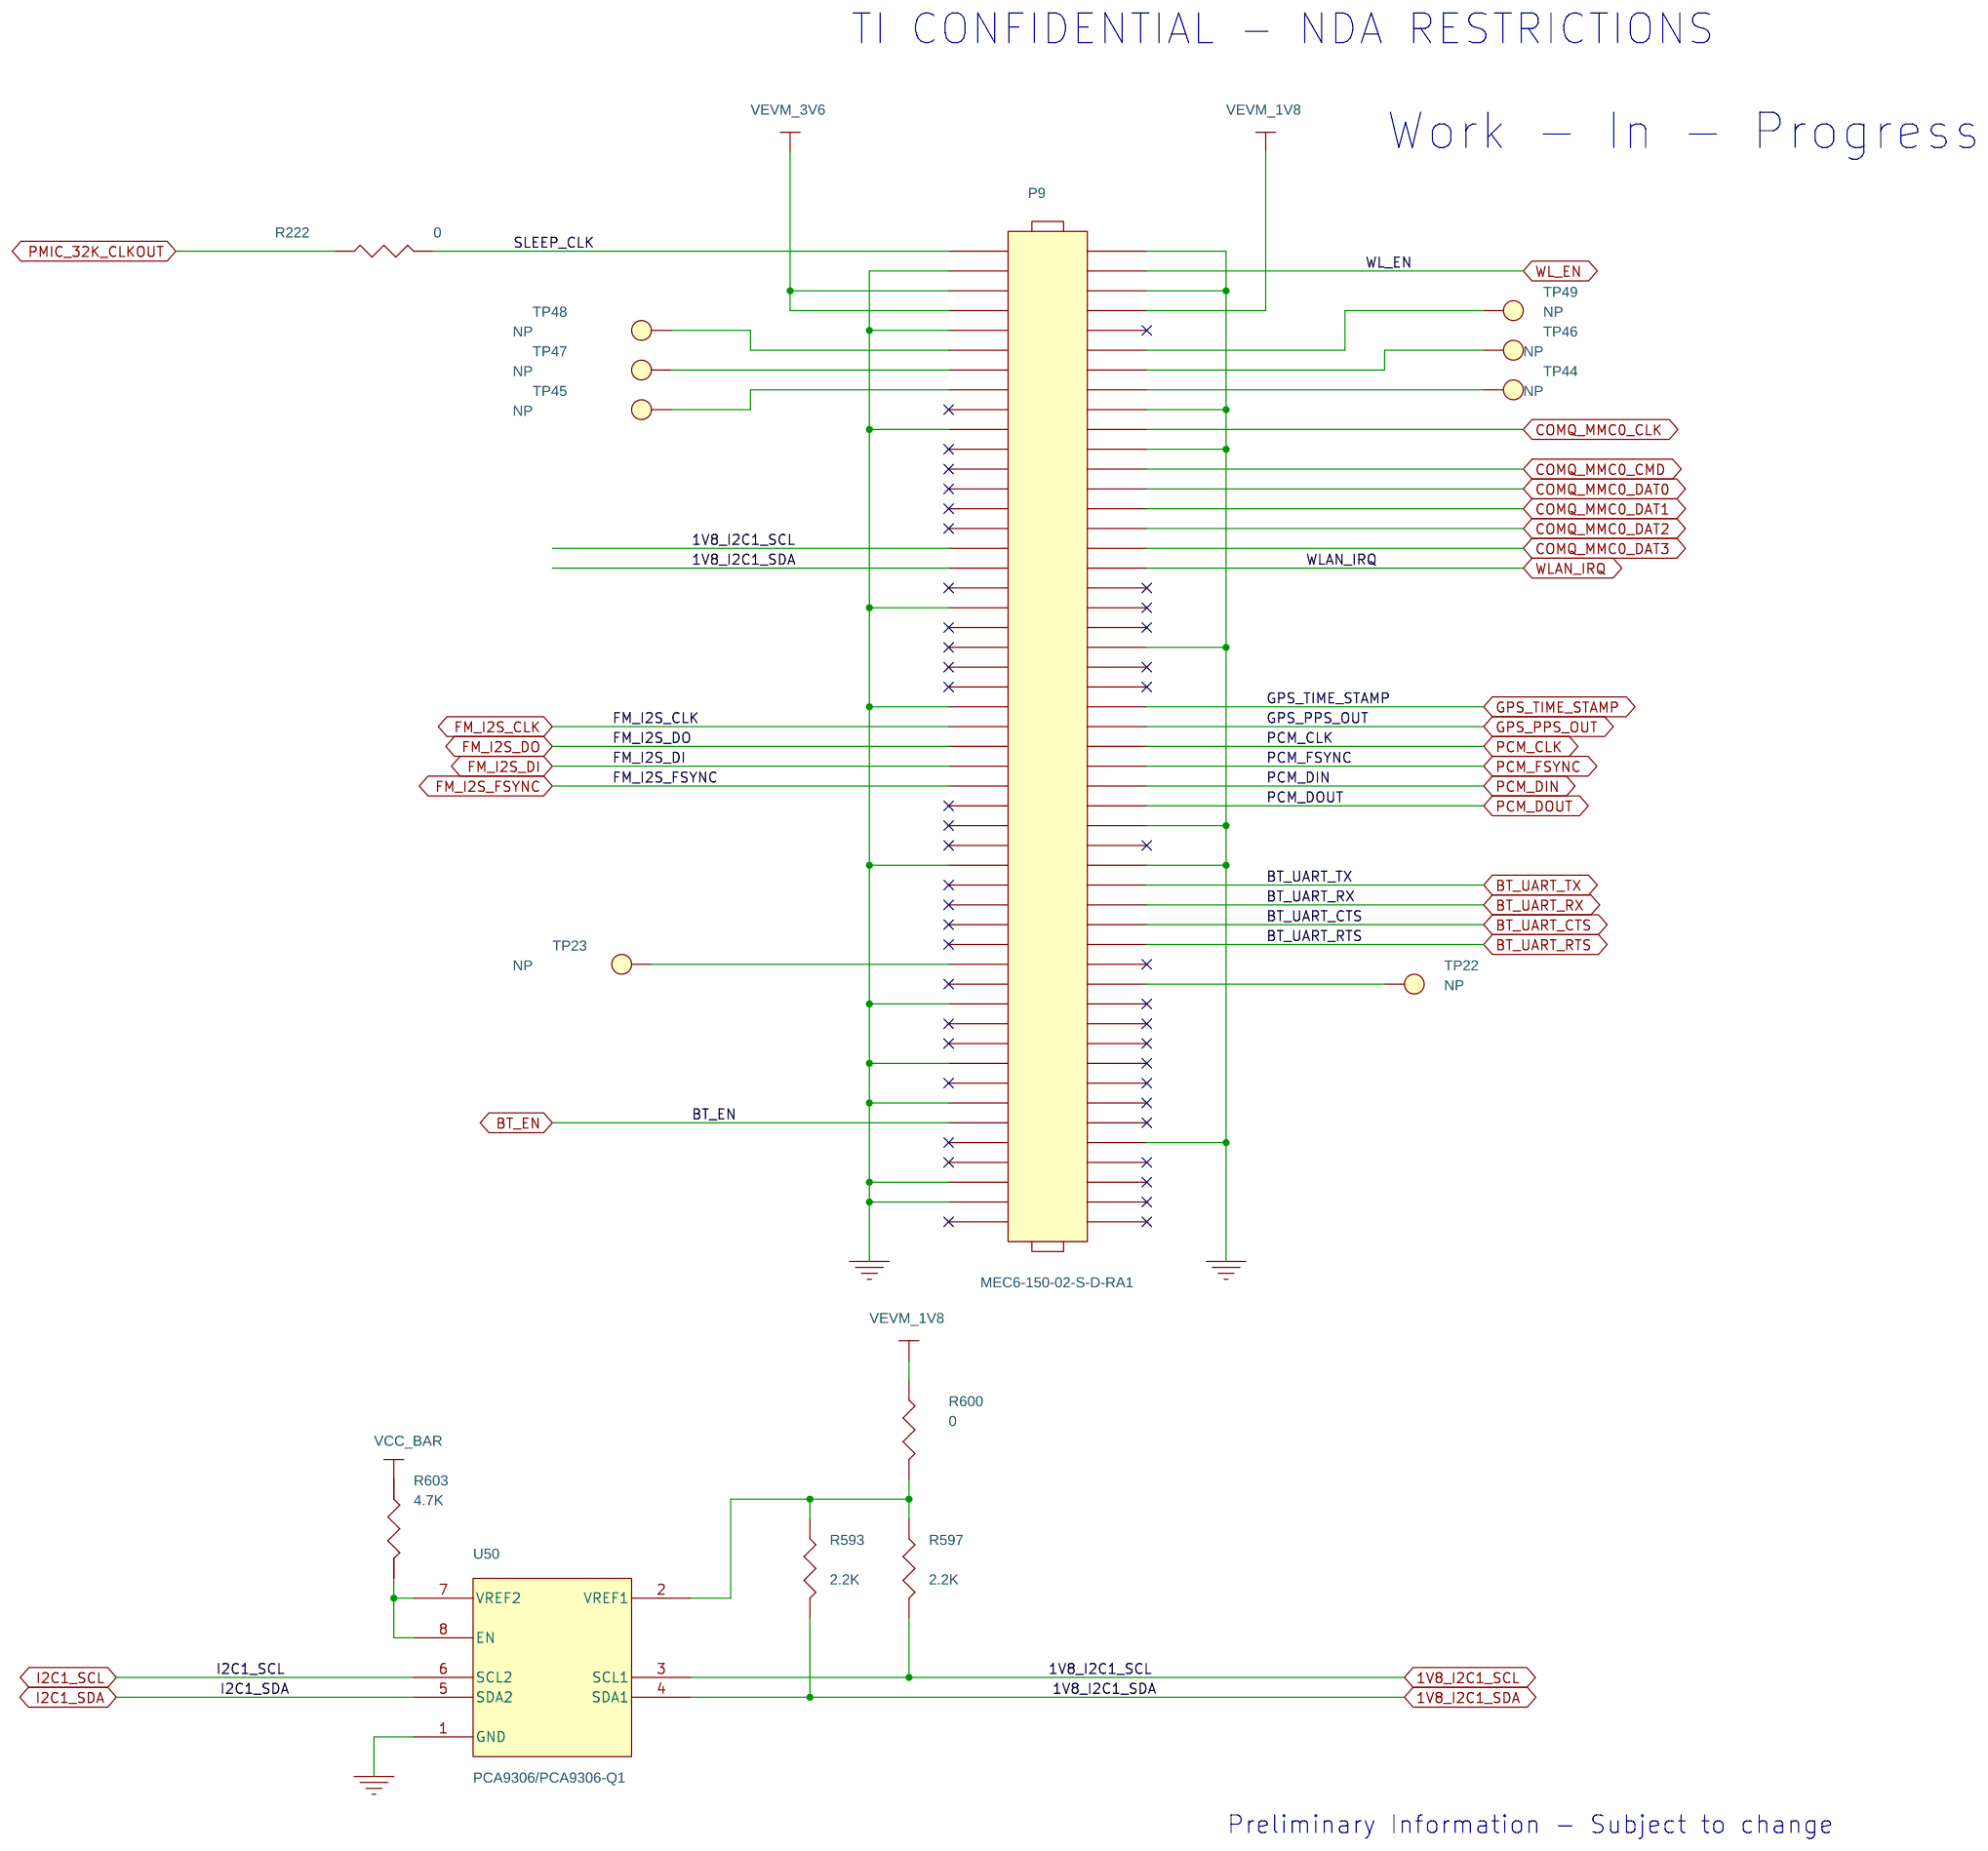
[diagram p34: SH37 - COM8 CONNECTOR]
36 SH38 - COM8 POWER: size B; rev: A
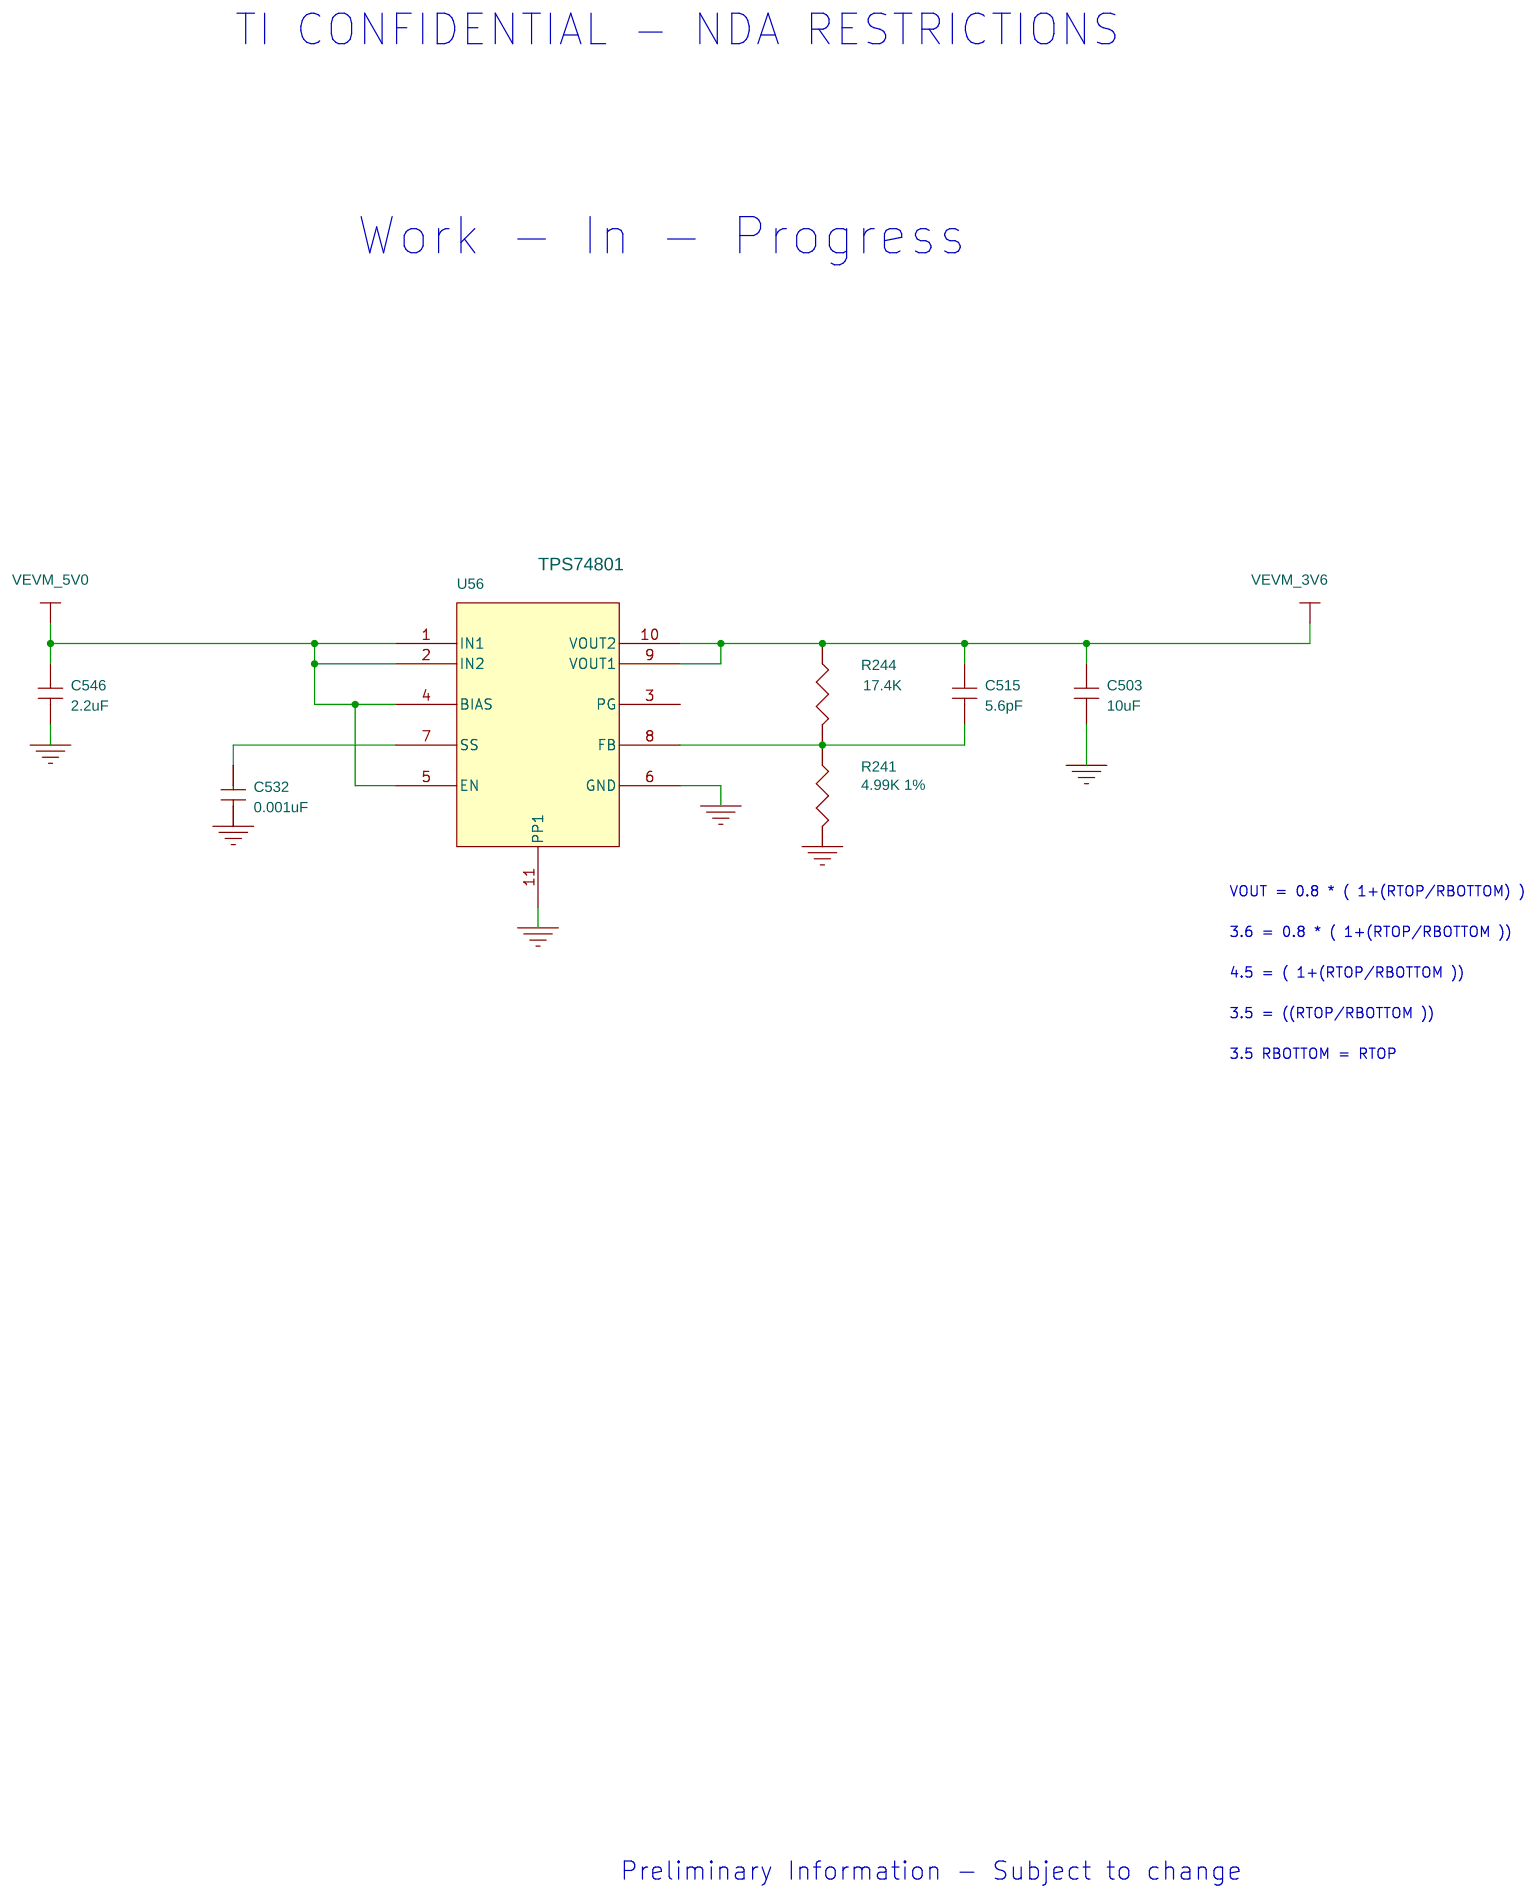
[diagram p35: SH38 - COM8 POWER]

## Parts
sheet SH28 - DDR3 BANK1 CAPS
C182  0.22uF  [c402-25]
C183  0.22uF  [c402-25]
C193  0.22uF  [c402-25]
C194  0.22uF  [c402-25]
C210  10uF  [c805-35x60]
C211  10uF  [c805-35x60]
C212  10uF  [c805-35x60]
C213  10uF  [c603-35x45]
C214  10uF  [c805-35x60]
C580  0.22uF  [c402-25]
C583  0.22uF  [c402-25]
C587  0.22uF  [c402-25]
C588  0.22uF  [c402-25]
C590  0.22uF  [c402-25]
C591  0.22uF  [c402-25]
C594  0.22uF  [c402-25]
C597  0.22uF  [c402-25]
C598  0.22uF  [c402-25]
C600  0.22uF  [c402-25]
C602  0.22uF  [c402-25]
C603  0.22uF  [c402-25]
C605  0.22uF  [c402-25]
C606  0.22uF  [c402-25]
C608  0.22uF  [c402-25]
C609  0.22uF  [c402-25]
C610  0.22uF  [c402-25]
C611  0.22uF  [c402-25]
C612  0.22uF  [c402-25]
C613  0.22uF  [c402-25]
C614  0.22uF  [c402-25]
C621  0.22uF  [c402-25]
C622  0.22uF  [c402-25]
C623  0.22uF  [c402-25]
C624  0.22uF  [c402-25]
C625  0.22uF  [c402-25]
C632  0.22uF  [c402-25]
C633  0.22uF  [c402-25]
C638  0.22uF  [c402-25]
C639  0.22uF  [c402-25]
C640  0.22uF  [c402-25]
C641  0.22uF  [c402-25]
sheet SH29 - DDR3 EMIF1 TERM
C164  0.22uF  [c603-35x45]
C165  0.22uF  [c603-35x45]
C175  0.22uF  [c603-35x45]
C180  0.22uF  [c603-35x45]
C206  0.22uF  [c603-35x45]
C207  0.22uF  [c603-35x45]
C599  0.1uF  [c402-25]
C627  0.22uF  [c603-35x45]
C635  0.22uF  [c603-35x45]
C643  0.22uF  [c603-35x45]
C654  0.22uF  [c603-35x45]
C662  0.22uF  [c603-35x45]
C663  0.22uF  [c603-35x45]
R684  49.9/1%  [r402-25]
R687  49.9/1%  [r402-25]
R689  49.9-1%  [r402-25]
RN2  R-PACK4-47  [rpak8-10x25-28v]
RN4  R-PACK4-47  [rpak8-10x25-28v]
RN6  R-PACK4-47  [rpak8-10x25-28v]
RN13  R-PACK4-47  [rpak8-10x25-28v]
RN15  R-PACK4-47  [rpak8-10x25-28v]
RN17  R-PACK4-47  [rpak8-10x25-28v]
sheet SH30 - DDR3 EMIF2 TESTPOINTS
TP2MA1  TP_VIA_MEM0  [tp1-18rd8]
TP2MA2  TP_VIA_MEM0  [tp1-18rd8]
TP2MA3  TP_VIA_MEM0  [tp1-18rd8]
TP2MA4  TP_VIA_MEM0  [tp1-18rd8]
TP2MA5  TP_VIA_MEM0  [tp1-18rd8]
TP2MA6  TP_VIA_MEM0  [tp1-18rd8]
TP2MA7  TP_VIA_MEM0  [tp1-18rd8]
TP2MA8  TP_VIA_MEM0  [tp1-18rd8]
TP2MA9  TP_VIA_MEM0  [tp1-18rd8]
TP2MA10  TP_VIA_MEM0  [tp1-18rd8]
TP2MA11  TP_VIA_MEM0  [tp1-18rd8]
TP2MA12  TP_VIA_MEM0  [tp1-18rd8]
TP2MA13  TP_VIA_MEM0  [tp1-18rd8]
TP2MA14  TP_VIA_MEM0  [tp1-18rd8]
TP2MA15  TP_VIA_MEM0  [tp1-18rd8]
TP2MA16  TP_VIA_MEM0  [tp1-18rd8]
TP2MA17  TP_VIA_MEM0  [tp1-18rd8]
TP2MA18  TP_VIA_MEM0  [tp1-18rd8]
TP2MA19  TP_VIA_MEM0  [tp1-18rd8]
TP2MA20  TP_VIA_MEM0  [tp1-18rd8]
TP2MA21  TP_VIA_MEM0  [tp1-18rd8]
TP2MA22  TP_VIA_MEM0  [tp1-18rd8]
TP2MA23  TP_VIA_MEM0  [tp1-18rd8]
TP2MA24  TP_VIA_MEM0  [tp1-18rd8]
TP2MA25  TP_VIA_MEM0  [tp1-18rd8]
TP2MA26  TP_VIA_MEM0  [tp1-18rd8]
TP2MA27  TP_VIA_MEM0  [tp1-18rd8]
TP2MB1  TP_VIA_MEM1  [tp1-18rd8]
TP2MB2  TP_VIA_MEM1  [tp1-18rd8]
TP2MB3  TP_VIA_MEM1  [tp1-18rd8]
TP2MB4  TP_VIA_MEM1  [tp1-18rd8]
TP2MB5  TP_VIA_MEM1  [tp1-18rd8]
TP2MB6  TP_VIA_MEM1  [tp1-18rd8]
TP2MB7  TP_VIA_MEM1  [tp1-18rd8]
TP2MB8  TP_VIA_MEM1  [tp1-18rd8]
TP2MB9  TP_VIA_MEM1  [tp1-18rd8]
TP2MB10  TP_VIA_MEM1  [tp1-18rd8]
TP2MB11  TP_VIA_MEM1  [tp1-18rd8]
TP2MB12  TP_VIA_MEM1  [tp1-18rd8]
TP2MB13  TP_VIA_MEM1  [tp1-18rd8]
TP2MB14  TP_VIA_MEM1  [tp1-18rd8]
TP2MB15  TP_VIA_MEM1  [tp1-18rd8]
TP2MB16  TP_VIA_MEM1  [tp1-18rd8]
TP2MB17  TP_VIA_MEM1  [tp1-18rd8]
TP2MB18  TP_VIA_MEM1  [tp1-18rd8]
TP2MB19  TP_VIA_MEM1  [tp1-18rd8]
TP2MB20  TP_VIA_MEM1  [tp1-18rd8]
TP2MB21  TP_VIA_MEM1  [tp1-18rd8]
TP2MB22  TP_VIA_MEM1  [tp1-18rd8]
TP2MB23  TP_VIA_MEM1  [tp1-18rd8]
TP2MB24  TP_VIA_MEM1  [tp1-18rd8]
TP2MB25  TP_VIA_MEM1  [tp1-18rd8]
TP2MB26  TP_VIA_MEM1  [tp1-18rd8]
TP2MB27  TP_VIA_MEM1  [tp1-18rd8]
sheet SH31 - DDR3 EMIF2 BANK 2
C177  0.22uF  [c603-35x45]
C178  0.22uF  [c603-35x45]
C197  0.22uF  [c603-35x45]
C198  0.22uF  [c603-35x45]
C628  0.22uF  [c603-35x45]
C629  0.22uF  [c603-35x45]
C651  0.22uF  [c603-35x45]
C652  0.22uF  [c603-35x45]
R288  240  [r402-25]
R289  240  [r402-25]
R694  240  [r402-25]
R695  240  [r402-25]
U68  MT41K256M8DA-15E:M ATT  [bga6x13-p8-ra-pkg]
U69  MT41K256M8DA-15E:M ATT  [bga6x13-p8-ra-pkg]
U115  MT41K256M8DA-15E:M ATT  [bga6x13-p8-ra-pkg]
U116  MT41K256M8DA-15E:M ATT  [bga6x13-p8-ra-pkg]
sheet SH32 - DDR3 BANK2 CAPS
C158  0.22uF  [c603-35x45]
C159  0.22uF  [c603-35x45]
C160  0.22uF  [c603-35x45]
C161  0.22uF  [c603-35x45]
C162  0.22uF  [c603-35x45]
C163  0.22uF  [c603-35x45]
C169  0.22uF  [c603-35x45]
C170  0.22uF  [c603-35x45]
C171  0.22uF  [c603-35x45]
C172  0.22uF  [c603-35x45]
C184  0.22uF  [c603-35x45]
C185  0.22uF  [c603-35x45]
C189  0.22uF  [c603-35x45]
C190  0.22uF  [c603-35x45]
C195  0.22uF  [c603-35x45]
C196  0.22uF  [c603-35x45]
C199  0.22uF  [c603-35x45]
C200  0.22uF  [c603-35x45]
C581  0.22uF  [c603-35x45]
C582  0.22uF  [c603-35x45]
C585  0.22uF  [c603-35x45]
C586  0.22uF  [c603-35x45]
C592  0.22uF  [c603-35x45]
C593  0.22uF  [c603-35x45]
C595  0.22uF  [c603-35x45]
C596  0.22uF  [c603-35x45]
C615  0.22uF  [c603-35x45]
C616  0.22uF  [c603-35x45]
C630  0.22uF  [c603-35x45]
C631  0.22uF  [c603-35x45]
C636  0.22uF  [c603-35x45]
C637  0.22uF  [c603-35x45]
C644  0.22uF  [c603-35x45]
C645  0.22uF  [c603-35x45]
C649  0.22uF  [c603-35x45]
C650  0.22uF  [c603-35x45]
C664  0.22uF  [c603-35x45]
C665  10uF  [c805-35x60]
C666  0.22uF  [c603-35x45]
C667  0.22uF  [c603-35x45]
C668  0.22uF  [c603-35x45]
C669  0.22uF  [c603-35x45]
C670  10uF  [c805-35x60]
C671  0.22uF  [c603-35x45]
C672  0.22uF  [c603-35x45]
C673  10uF  [c805-35x60]
C674  0.22uF  [c603-35x45]
C675  0.22uF  [c603-35x45]
C676  0.22uF  [c603-35x45]
C677  0.22uF  [c603-35x45]
C678  10uF  [c805-35x60]
C679  0.22uF  [c603-35x45]
sheet SH33 - DDR3 EMIF2 TERM
C166  0.22uF  [c603-35x45]
C167  0.22uF  [c603-35x45]
C176  0.22uF  [c603-35x45]
C181  0.22uF  [c603-35x45]
C208  0.22uF  [c603-35x45]
C209  0.22uF  [c603-35x45]
C601  0.1uF  [c402-25]
C626  0.22uF  [c603-35x45]
C634  0.22uF  [c603-35x45]
C642  0.22uF  [c603-35x45]
C653  0.22uF  [c603-35x45]
C660  0.22uF  [c603-35x45]
C661  0.22uF  [c603-35x45]
R286  49.9/1%  [r402-25]
R685  49.9/1%  [r402-25]
R688  49.9/1%  [r402-25]
RN3  R-PACK4-47  [rpak8-10x25-28v]
RN5  R-PACK4-47  [rpak8-10x25-28v]
RN7  R-PACK4-47  [rpak8-10x25-28v]
RN12  R-PACK4-47  [rpak8-10x25-28v]
RN14  R-PACK4-47  [rpak8-10x25-28v]
RN16  R-PACK4-47  [rpak8-10x25-28v]
sheet SH33 - HDMI OUTPUT CONNECTOR
C1  0.1uF  [c402-25]
C3  0.1uF  [c402-25]
C230  0.1uF  [c402-25]
FL5  DLW21SN900HQ2  [EMI-36X15-DLW21-rdpads]
FL6  DLW21SN900HQ2  [EMI-36X15-DLW21-rdpads]
FL7  DLW21SN900HQ2  [EMI-36X15-DLW21-rdpads]
FL8  DLW21SN900HQ2  [EMI-36X15-DLW21-rdpads]
P4  HDMI-RA-19-TYPEA  [hdmi-smt-w-flange-rdpads]
R6  NO-POP  [r402-25]
R7  NO-POP  [r402-25]
R305  10K  [r201-6p6spc]
R321  10K  [r402-25]
R322  10K  [r402-25]
R517  NO-POP  [r201-6p6spc]
R711  NO-POP  [r201-6p6spc]
R712  NO-POP  [r201-6p6spc]
R713  NO-POP  [r201-6p6spc]
U133  tpd1e05u06  [dpy-rdpads]
U134  tpd1e05u06  [dpy-rdpads]
U135  tpd1e05u06  [dpy-rdpads]
U136  tpd1e05u06  [dpy-rdpads]
U137  tpd1e05u06  [dpy-rdpads]
U138  tpd1e05u06  [dpy-rdpads]
U139  tpd1e05u06  [dpy-rdpads]
U140  tpd1e05u06  [dpy-rdpads]
U141  TPD12S016RKTR  [rkt24]
sheet SH34 - USB1
C79  10uF  [c603-35x45]
C80  0.1uF  [c402-25]
C325  10uF  [c603-35x45]
FL1  DLW21SN121HQ2  [EMI-36X15-DLW21]
L8  BLM21PG221SN1  [l805-35x60]
R1  10K  [r402-25]
R154  100K  [r402-25]
R301  10K  [r402-25]
R481  10K  [r402-25]
R771  10K  [r402-25]
TP2  NP  [tp20]
TP27  NP  [tp20]
U36  TPS2065D  [so8-25x75]
U73  TPD4S014DSQ  [dsq10-son]
sheet SH35 - USB2
C86  10uF  [c603-35x45]
C87  0.1uF  [c402-25]
C340  10uF  [c603-35x45]
FL4  DLW21SN121HQ2  [EMI-36X15-DLW21]
L12  BLM21PG221SN1  [l805-35x60]
R179  100K  [r402-25]
R302  10K  [r402-25]
R307  10K  [r402-25]
R532  10K  [r402-25]
R770  10K  [r402-25]
TP1  NP  [tp20]
TP39  NP  [tp20]
U43  TPS2065D  [so8-25x75]
U72  TPD4S014DSQ  [dsq10-son]
sheet SH36 - COM8 LEVEL TRANSLATORS
C331  0.1uF  [c402-25]
C332  0.1uF  [c402-25]
C335  0.1uF  [c402-25]
C344  0.1uF  [c402-25]
C345  0.1uF  [c402-25]
C351  0.1uF  [c402-25]
C404  0.1uF  [c402-25]
C405  0.1uF  [c402-25]
C411  0.1uF  [c402-25]
C446  0.1uF  [c402-25]
C447  0.1uF  [c402-25]
C448  0.1uF  [c402-25]
C472  0.1uF  [c402-25]
C479  0.1uF  [c402-25]
R157  NP  [r402-25]
R178  NP  [r402-25]
R196  NP  [r402-25]
R200  NP  [r402-25]
R515  0  [r402-25]
R519  10K  [r402-25]
R520  10K  [r402-25]
R521  10K  [r402-25]
R522  10K  [r402-25]
R523  10K  [r402-25]
R524  10K  [r402-25]
R528  10K  [r402-25]
R548  0  [r402-25]
R558  20K  [r402-25]
R559  20K  [r402-25]
R560  20K  [r402-25]
R561  20K  [r402-25]
R562  20K  [r402-25]
R581  10K  [r402-25]
R584  10K  [r402-25]
R587  NP  [r402-25]
R714  0  [r201-6p6spc]
R715  0  [r201-6p6spc]
U35  SN74AVC8T245RHL  [rhl24-pvqfn-ti]
U41  SN74AVC4T245RGYR  [rgy16-12x34]
U46  SN74AVC8T245RHL  [rhl24-pvqfn-ti]
U48  SN74AVC4T245RGYR  [rgy16-12x34]
U100  TXS0108EPW  [pw20-14x70]
U104  SN74LVC1T45  [DCK-17X60-6]
sheet SH37 - COM8 CONNECTOR
P9  MEC6-150-02-S-D-RA1  [mec6-150-ra1]
R222  0  [r402-25]
R593  2.2K  [r402-25]
R597  2.2K  [r402-25]
R600  0  [r402-25]
R603  4.7K  [r402-25]
TP22  NP  [tp20]
TP23  NP  [tp20]
TP44  NP  [tp20]
TP45  NP  [tp20]
TP46  NP  [tp20]
TP47  NP  [tp20]
TP48  NP  [tp20]
TP49  NP  [tp20]
U50  PCA9306/PCA9306-Q1  [dcu8-10x50]
sheet SH38 - COM8 POWER
C503  10uF  [c603-35x45]
C515  5.6pF  [c402-25]
C532  0.001uF  [c402-25]
C546  2.2uF  [c603-35x45]
R241  4.99K 1%  [r603-35x45]
R244  17.4K  [r603-35x45]
U56  TPS74801  [drc10-11x33]

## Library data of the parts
C182 C183 C193 C583 C588 C591 C594 C597 C598 C600 C602 C603 C605 C606 C610-C614 C621-C625 C632 C633 C638-C641 = CAP_NP_0: Part #: 103214-1220R; SD PCB Footprint: EIA0402
C159-C163 C169-C172 C177 C178 C184 C185 C189 C190 C194-C200 C581 C582 C585-C587 C590 C592 C593 C595 C596 C608 C615 C616 C628-C631 C636 C637 C644 C645 C649-C652 C664 C666-C669 C671 C672 C674-C677 C679 = CAP_NP_0: Part #: 103214-1220R
C79 C86 C210-C214 C325 C340 C665 C670 C673 C678 = CAP: Part #: 102963-0101R
C158 C580 C609 = CAP: Part #: 103214-1220R
C164 C165 C175 C180 C206 C207 C627 C635 C643 C654 C662 C663 = CAP_NP_0: Part #: 101587-1220R; SD PCB Footprint: EIA0402
C599 = SC10N16V2KX_0: @CAP SMD 0402 10nf 16V ??10% X7R; Part #: 101587-1100R
R684 R687 = 1KR2F: @RES SMD 0402 1K·[ ??1% 1/16W; Part #: 102145-4990R
R286 R689 = R: Part #: 102145-4990R
RN2-RN7 RN12-RN17 = R-Pak4_0: Part #: 101327-4700R
TP2MA1-TP2MA27 = TP_VIA_MEM0_0: Part #: TP-18RD8-NO-POP
TP2MB1-TP2MB27 = TP_VIA_MEM1_0: Part #: TP-18RD8-NO-POP
R288 R289 R694 R695 = R: Part #: 101370-2401R
U68 U69 U115 U116 = EDJ1108DBSE_1: Part #: 104177-0125R
C166 C167 C176 C181 C208 C209 C626 C634 C642 C653 C660 C661 = CAP_NP_0: Part #: 101587-1220R
C601 = SC10N16V2KX_0: Part #: 101587-1100R
R685 R688 = 1KR2F_0: Part #: 102145-4990R
C1 C3 C80 C87 C230 C405 C411 = CAP_NP: Part #: 101587-1100R
FL5-FL8 = DLW21SN900HQ2: Part #: 104184-9000R
P4 = HDMI-RA-19_0: Part #: 103169-0001R
R6 R7 R157 R178 R196 R200 R587 = R: Part #: R0402-NOPOP
R305 = R: Part #: 103158-1003R
R1 R301 R302 R307 R321 R322 R481 R519-R524 R528 R532 R581 R584 R770 R771 = R: Part #: 101370-1003R
R517 R711-R713 = R: Part #: R0201-NOPOP
U133-U140 = tpd1e05u06: Part #: 104410-0001R
U141 = TPD12S016RKTR_QFN24_3: Part #: 103797-0001R
FL1 FL4 = DLW21SN121HQ2: Part #: 104184-1201R
L8 L12 = INDUCTOR_3: Part #: 101228-2201R
R154 R179 = R: Part #: 101370-1004R
TP1 TP2 TP27 TP39 = TestPoint1_0: Part #: SMT-TP020
U36 U43 = tps2061_1: Part #: 102810-0001R
U72 U73 = TPD4S014DSQ: Part #: 104147-0001R
C331 C332 C335 C344 C345 C351 C404 C446-C448 C472 C479 = CAP: Part #: 101587-1100R
R222 R515 R548 R600 = R: Part #: 101370-0001R
R558-R562 = R: Part #: 101370-2003R
R714 R715 = R: Part #: 103158-0001R
U35 U46 = SN74AVC8T245_1: Part #: 102708-0001R
U41 U48 = SN74AVC4T245RGYR_0: Part #: 102649-0245R
U100 = TXB0108PWR_0: Part #: 103666-0001R
U104 = TMP_1: Part #: 102156-0001R
P9 = HEADER_50x2: Part #: 103626-0050R
R593 R597 = RESISTOR_0: Part #: 101370-2202R
R603 = RESISTOR_0: Part #: 101370-4702R
TP22 TP23 TP44-TP49 = TESTPOINT: Part #: SMT-TP020
U50 = PCA9306: Part #: 103282-0001R
C503 = CAP_NP: Part #: 102963-0101R
C515 = Cap_100nF_Cermc_16V_10%_603_3: Part #: 101782-1565R
C532 = CAP_NP: Part #: 102058-1102R
C546 = CAP_NP: Part #: 102965-0220R
R241 = R_3: Part #: 100642-4992R
R244 = R_3: Part #: 100642-1743R
U56 = U-TPS78601_AJUST_-_1_3.5A_LDO: Part #: 104335-0001R

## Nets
1V8_I2C1_SCL: P9.31 R597.2 U50.3(SCL1) ; also on sheet 40
1V8_I2C1_SDA: P9.33 R593.2 U50.4(SDA1) ; also on sheet 40
GND: C1.2 C3.2 C79.2 C80.2 C86.2 C87.2 C158.2 C159.2 C160.2 C161.2 C162.2 C163.2 C169.2 C170.2 C171.2 C172.2 C177.2 C178.2 C182.2 C183.2 C184.2 C185.2 C189.2 C190.2 C193.2 C194.2 C195.2 C196.2 C199.2 C200.2 C210.2 C211.2 C212.2 C213.2 C214.2 C230.2 C325.2 C331.2 C332.2 C335.2 C340.2 C344.2 C345.2 C351.2 C404.2 C405.2 C411.2 C446.2 C447.2 C448.2 C472.2 C479.2 C503.2 C532.2 C546.2 C580.2 C581.2 C582.2 C583.2 C585.2 C586.2 C587.2 C588.2 C590.2 C591.2 C592.2 C593.2 C594.2 C595.2 C596.2 C597.2 C598.2 C600.2 C602.2 C603.2 C605.2 C606.2 C608.2 C609.2 C610.2 C611.2 C612.2 C613.2 C614.2 C615.2 C616.2 C621.2 C622.2 C623.2 C624.2 C625.2 C628.2 C629.2 C630.2 C631.2 C632.2 C633.2 C636.2 C637.2 C638.2 C639.2 C640.2 C641.2 C644.2 C645.2 C649.2 C650.2 C664.2 C665.2 C666.2 C667.2 C668.2 C669.2 C670.2 C671.2 C672.2 C673.2 C674.2 C675.2 C676.2 C677.2 C678.2 C679.2 P4.2(D2_SHIELD) P4.5(D1_SHIELD) P4.8(D0_SHIELD) P4.11(CK_SHIELD) P4.17(GND) P4.MTG1 P4.MTG2 P4.MTG3 P4.MTG4 P9.2 P9.3 P9.6 P9.9 P9.18 P9.19 P9.22 P9.37 P9.42 P9.47 P9.60 P9.63 P9.64 P9.77 P9.83 P9.87 P9.92 P9.95 P9.97 R154.2 R157.2 R178.2 R179.2 R196.2 R200.2 R241.2 R288.2 R289.2 R305.2 R481.1 R515.2 R532.1 R694.2 R695.2 R714.1 R715.2 U35.2(DIR) U35.11(GND) U35.12(GND) U35.13(GND) U35.25(PP) U36.1(GND) U41.7(2A2) U41.8(GND.1) U41.9(GND.2) U41.17(GND.3) U43.1(GND) U46.11(GND) U46.12(GND) U46.13(GND) U46.25(PP) U48.7(2A2) U48.8(GND.1) U48.9(GND.2) U48.17(GND.3) U50.1(GND) U56.6(GND) U56.11(PP1) U68.A1(VSS.1) U68.A8(VSS.2) U68.B1(VSS.3) U68.B2(VSSQ) U68.B8(VSSQ) U68.C9(VSSQ) U68.D1(VSSQ) U68.D8(VSS.4) U68.D9(VSSQ) U68.F2(VSS.5) U68.F8(VSS.6) U68.J1(VSS.7) U68.J9(VSS.8) U68.L1(VSS.9) U68.L9(VSS.10) U68.N1(VSS.11) U68.N9(VSS.12) U69.A1(VSS.1) U69.A8(VSS.2) U69.B1(VSS.3) U69.B2(VSSQ) U69.B8(VSSQ) U69.C9(VSSQ) U69.D1(VSSQ) U69.D8(VSS.4) U69.D9(VSSQ) U69.F2(VSS.5) U69.F8(VSS.6) U69.J1(VSS.7) U69.J9(VSS.8) U69.L1(VSS.9) U69.L9(VSS.10) U69.N1(VSS.11) U69.N9(VSS.12) U72.8(GND) U72.11(PWR_PAD) U73.8(GND) U73.11(PWR_PAD) U100.11(GND1) U100.17(B3) U100.18(B2) U100.20(B1) U104.2(GND) U104.5(DIR) U115.A1(VSS.1) U115.A8(VSS.2) U115.B1(VSS.3) U115.B2(VSSQ) U115.B8(VSSQ) U115.C9(VSSQ) U115.D1(VSSQ) U115.D8(VSS.4) U115.D9(VSSQ) U115.F2(VSS.5) U115.F8(VSS.6) U115.J1(VSS.7) U115.J9(VSS.8) U115.L1(VSS.9) U115.L9(VSS.10) U115.N1(VSS.11) U115.N9(VSS.12) U116.A1(VSS.1) U116.A8(VSS.2) U116.B1(VSS.3) U116.B2(VSSQ) U116.B8(VSSQ) U116.C9(VSSQ) U116.D1(VSSQ) U116.D8(VSS.4) U116.D9(VSSQ) U116.F2(VSS.5) U116.F8(VSS.6) U116.J1(VSS.7) U116.J9(VSS.8) U116.L1(VSS.9) U116.L9(VSS.10) U116.N1(VSS.11) U116.N9(VSS.12) U133.1(IO) U134.1(IO) U135.1(IO) U136.1(IO) U137.1(IO) U138.1(IO) U139.1(IO) U140.1(IO) U141.5(GND1) U141.13(GND2) U141.18(GND3) ; also on sheet 3 5 7 8 9 11 12 13 14 15 16 17 18 19 20 21 22 24 37 38 39 40 41 42 43 44 45 46 47 48 49 50 51 52 55 57
VBUS_USB1: C80.1 L8.1 U73.9(VBUS.2) U73.10(VBUS.1)
VBUS_USB1_SW: C79.1 L8.2 R154.1 U36.6(OUT3) U36.7(OUT2) U36.8(OUT1)
VBUS_USB2: C87.1 L12.1 U72.9(VBUS.2) U72.10(VBUS.1)
VBUS_USB2_SW: C86.1 L12.2 R179.1 U43.6(OUT3) U43.7(OUT2) U43.8(OUT1)
VDD_DDR: C158.1 C159.1 C160.1 C161.1 C162.1 C163.1 C164.2 C165.2 C166.2 C167.2 C169.1 C170.1 C171.1 C172.1 C175.2 C176.2 C180.2 C181.2 C182.1 C183.1 C184.1 C185.1 C189.1 C190.1 C193.1 C194.1 C195.1 C196.1 C197.2 C198.2 C199.1 C200.1 C206.2 C207.2 C208.2 C209.2 C210.1 C211.1 C212.1 C213.1 C214.1 C580.1 C581.1 C582.1 C583.1 C585.1 C586.1 C587.1 C588.1 C590.1 C591.1 C592.1 C593.1 C594.1 C595.1 C596.1 C597.1 C598.1 C599.2 C600.1 C601.2 C602.1 C603.1 C605.1 C606.1 C608.1 C609.1 C610.1 C611.1 C612.1 C613.1 C614.1 C615.1 C616.1 C621.1 C622.1 C623.1 C624.1 C625.1 C626.2 C627.2 C630.1 C631.1 C632.1 C633.1 C634.2 C635.2 C636.1 C637.1 C638.1 C639.1 C640.1 C641.1 C642.2 C643.2 C644.1 C645.1 C649.1 C650.1 C651.2 C652.2 C653.2 C654.2 C660.2 C661.2 C662.2 C663.2 C664.1 C665.1 C666.1 C667.1 C668.1 C669.1 C670.1 C671.1 C672.1 C673.1 C674.1 C675.1 C676.1 C677.1 C678.1 C679.1 U68.A2(VDD.1) U68.A9(VDD.2) U68.B9(VDDQ.1) U68.C1(VDDQ.2) U68.D7(VDD.3) U68.E2(VDDQ.3) U68.E9(VDDQ.4) U68.G2(VDD.4) U68.G8(VDD.5) U68.K1(VDD.6) U68.K9(VDD.7) U68.M1(VDD.8) U68.M9(VDD.9) U69.A2(VDD.1) U69.A9(VDD.2) U69.B9(VDDQ.1) U69.C1(VDDQ.2) U69.D7(VDD.3) U69.E2(VDDQ.3) U69.E9(VDDQ.4) U69.G2(VDD.4) U69.G8(VDD.5) U69.K1(VDD.6) U69.K9(VDD.7) U69.M1(VDD.8) U69.M9(VDD.9) U115.A2(VDD.1) U115.A9(VDD.2) U115.B9(VDDQ.1) U115.C1(VDDQ.2) U115.D7(VDD.3) U115.E2(VDDQ.3) U115.E9(VDDQ.4) U115.G2(VDD.4) U115.G8(VDD.5) U115.K1(VDD.6) U115.K9(VDD.7) U115.M1(VDD.8) U115.M9(VDD.9) U116.A2(VDD.1) U116.A9(VDD.2) U116.B9(VDDQ.1) U116.C1(VDDQ.2) U116.D7(VDD.3) U116.E2(VDDQ.3) U116.E9(VDDQ.4) U116.G2(VDD.4) U116.G8(VDD.5) U116.K1(VDD.6) U116.K9(VDD.7) U116.M1(VDD.8) U116.M9(VDD.9) ; also on sheet 17 24 42 50
VDDR_VREFSTL: C177.1 C178.1 C197.1 C198.1 C628.1 C629.1 C651.1 C652.1 U68.E1(VREFDQ) U68.J8(VREFCA) U69.E1(VREFDQ) U69.J8(VREFCA) U115.E1(VREFDQ) U115.J8(VREFCA) U116.E1(VREFDQ) U116.J8(VREFCA) ; also on sheet 7 8 24 50
BT_EN: P9.89 U46.20(B2)
BT_UART_CTS: P9.70 U46.15(B7)
BT_UART_RTS: P9.72 U35.16(B6)
BT_UART_RX: P9.68 U46.14(B8)
BT_UART_TX: P9.66 U35.17(B5)
C_SPI1_CS3n: U141.24(CEC_A)
COMQ_MMC0_CLK: P9.20 U104.3(A)
COMQ_MMC0_CMD: P9.24 R559.2 U100.5(A4)
COMQ_MMC0_DAT0: P9.26 R560.2 U100.6(A5)
COMQ_MMC0_DAT1: P9.28 R561.2 U100.7(A6)
COMQ_MMC0_DAT2: P9.30 R562.2 U100.8(A7)
COMQ_MMC0_DAT3: P9.32 R558.2 U100.9(A8)
CON_USB1_DM: FL1.3 U73.6(D-)
CON_USB1_DP: FL1.2 U73.7(D+)
CON_USB2_DM: FL4.3 U72.6(D-)
CON_USB2_DP: FL4.2 U72.7(D+)
FM_I2S_CLK: P9.49 U48.13(1B1)
FM_I2S_DI: P9.53 U48.11(2B1)
FM_I2S_DO: P9.51 U35.18(B4)
FM_I2S_FSYNC: P9.55 U48.12(1B2)
GP5[4]: U46.4(A2)
GP5[5]: U35.5(A3)
GP5[6]: U46.6(A4)
GP5[7]: U35.3(A1)
GP5[8]: U46.5(A3)
GPS_PPS_OUT: P9.50 U35.19(B3)
GPS_TIME_STAMP: P9.48 U46.18(B4)
H_DDR1_A0: RN4.1(R1A) ; also on sheet 7 23 24
H_DDR1_A1: RN4.2(R2A) ; also on sheet 7 24
H_DDR1_A2: RN6.4(R4A) ; also on sheet 7 24
H_DDR1_A3: RN15.4(R4A) ; also on sheet 7 24
H_DDR1_A4: RN4.3(R3A) ; also on sheet 7 24
H_DDR1_A5: RN4.4(R4A) ; also on sheet 7 24
H_DDR1_A6: RN17.3(R3A) ; also on sheet 7 24
H_DDR1_A7: RN6.2(R2A) ; also on sheet 7 24
H_DDR1_A8: RN17.1(R1A) ; also on sheet 7 24
H_DDR1_A9: RN6.1(R1A) ; also on sheet 7 24
H_DDR1_A10: RN13.3(R3A) ; also on sheet 7 24
H_DDR1_A11: RN17.4(R4A) ; also on sheet 7 24
H_DDR1_A12: RN15.1(R1A) ; also on sheet 7 24
H_DDR1_A13: RN6.3(R3A) ; also on sheet 7 24
H_DDR1_A14: RN17.2(R2A) ; also on sheet 7 24
H_DDR1_A15: RN13.1(R1A) ; also on sheet 7 24
H_DDR1_BA0: RN2.4(R4A) ; also on sheet 7 24
H_DDR1_BA1: RN15.3(R3A) ; also on sheet 7 24
H_DDR1_BA2: RN15.2(R2A) ; also on sheet 7 24
H_DDR1_CASN: RN2.2(R2A) ; also on sheet 7 24
H_DDR1_CKE: R689.1 ; also on sheet 7 23 24
H_DDR1_CLK0: R684.1 ; also on sheet 7 24
H_DDR1_CLK0N: R687.1 ; also on sheet 7 24
H_DDR1_CSN0: RN2.3(R3A) ; also on sheet 7 24
H_DDR1_ODT0: RN2.1(R1A) ; also on sheet 7 24
H_DDR1_RASN: RN13.4(R4A) ; also on sheet 7 24
H_DDR1_WEN: RN13.2(R2A) ; also on sheet 7 24
H_DDR2_A0: RN14.1(R1A) TP2MA15.1 TP2MB15.1 U68.K3(A0) U69.K3(A0) U115.K3(A0) U116.K3(A0) ; also on sheet 8
H_DDR2_A1: RN16.4(R4A) TP2MA19.1 TP2MB19.1 U68.L7(A1) U69.L7(A1) U115.L7(A1) U116.L7(A1) ; also on sheet 8
H_DDR2_A2: RN5.3(R3A) TP2MA20.1 TP2MB20.1 U68.L3(A2) U69.L3(A2) U115.L3(A2) U116.L3(A2) ; also on sheet 8
H_DDR2_A3: RN5.1(R1A) TP2MA14.1 TP2MB14.1 U68.K2(A3) U69.K2(A3) U115.K2(A3) U116.K2(A3) ; also on sheet 8
H_DDR2_A4: RN5.4(R4A) TP2MA17.1 TP2MB17.1 U68.L8(A4) U69.L8(A4) U115.L8(A4) U116.L8(A4) ; also on sheet 8
H_DDR2_A5: RN5.2(R2A) TP2MA18.1 TP2MB18.1 U68.L2(A5) U69.L2(A5) U115.L2(A5) U116.L2(A5) ; also on sheet 8
H_DDR2_A6: RN7.3(R3A) TP2MA24.1 TP2MB24.1 U68.M8(A6) U69.M8(A6) U115.M8(A6) U116.M8(A6) ; also on sheet 8
H_DDR2_A7: RN16.3(R3A) TP2MA23.1 TP2MB23.1 U68.M2(A7) U69.M2(A7) U115.M2(A7) U116.M2(A7) ; also on sheet 8
H_DDR2_A8: RN16.1(R1A) TP2MA27.1 TP2MB27.1 U68.N8(A8) U69.N8(A8) U115.N8(A8) U116.N8(A8) ; also on sheet 8
H_DDR2_A9: RN7.1(R1A) TP2MA21.1 TP2MB21.1 U68.M3(A9) U69.M3(A9) U115.M3(A9) U116.M3(A9) ; also on sheet 8
H_DDR2_A10: RN3.1(R1A) TP2MA7.1 TP2MB7.1 U68.H7(A10/AP) U69.H7(A10/AP) U115.H7(A10/AP) U116.H7(A10/AP) ; also on sheet 8
H_DDR2_A11: RN7.2(R2A) TP2MA22.1 TP2MB22.1 U68.M7(A11) U69.M7(A11) U115.M7(A11) U116.M7(A11) ; also on sheet 8
H_DDR2_A12: RN14.3(R3A) TP2MA16.1 TP2MB16.1 U68.K7(A12/~{BC}) U69.K7(A12/~{BC}) U115.K7(A12/~{BC}) U116.K7(A12/~{BC}) ; also on sheet 8
H_DDR2_A13: RN16.2(R2A) TP2MA26.1 TP2MB26.1 U68.N3(A13) U69.N3(A13) U115.N3(A13) U116.N3(A13) ; also on sheet 8
H_DDR2_A14: RN7.4(R4A) TP2MA25.1 TP2MB25.1 U68.N7(A14/NC) U69.N7(A14/NC) U115.N7(A14/NC) U116.N7(A14/NC) ; also on sheet 8
H_DDR2_A15: RN3.3(R3A) TP2MA12.1 TP2MB12.1 U68.J7(A15/NC) U69.J7(A15/NC) U115.J7(A15/NC) U116.J7(A15/NC) ; also on sheet 8
H_DDR2_BA0: RN12.3(R3A) TP2MA10.1 TP2MB10.1 U68.J2(BA0) U69.J2(BA0) U115.J2(BA0) U116.J2(BA0) ; also on sheet 8
H_DDR2_BA1: RN14.2(R2A) TP2MA13.1 TP2MB13.1 U68.K8(BA1) U69.K8(BA1) U115.K8(BA1) U116.K8(BA1) ; also on sheet 8
H_DDR2_BA2: RN14.4(R4A) TP2MA11.1 TP2MB11.1 U68.J3(BA2) U69.J3(BA2) U115.J3(BA2) U116.J3(BA2) ; also on sheet 8
H_DDR2_CASN: RN12.2(R2A) TP2MA6.1 TP2MB6.1 U68.G3(~{CAS}) U69.G3(~{CAS}) U115.G3(~{CAS}) U116.G3(~{CAS}) ; also on sheet 8
H_DDR2_CKE: RN12.4(R4A) TP2MA1.1 TP2MB1.1 U68.G9(CKE) U69.G9(CKE) U115.G9(CKE) U116.G9(CKE) ; also on sheet 8
H_DDR2_CLK0: R685.1 TP2MA4.1 TP2MB4.1 U68.F7(CK) U69.F7(CK) U115.F7(CK) U116.F7(CK) ; also on sheet 8
H_DDR2_CLK0N: R688.1 TP2MA5.1 TP2MB5.1 U68.G7(~{CK}) U69.G7(~{CK}) U115.G7(~{CK}) U116.G7(~{CK}) ; also on sheet 8
H_DDR2_CSN0: RN12.1(R1A) TP2MA8.1 TP2MB8.1 U68.H2(~{CS}) U69.H2(~{CS}) U115.H2(~{CS}) U116.H2(~{CS}) ; also on sheet 8
H_DDR2_D0: U115.E7(DQ7) ; also on sheet 8
H_DDR2_D1: U115.D2(DQ6) ; also on sheet 8
H_DDR2_D2: U115.C8(DQ3) ; also on sheet 8
H_DDR2_D3: U115.E8(DQ5) ; also on sheet 8
H_DDR2_D4: U115.C7(DQ1) ; also on sheet 8
H_DDR2_D5: U115.E3(DQ4) ; also on sheet 8
H_DDR2_D6: U115.C2(DQ2) ; also on sheet 8
H_DDR2_D7: U115.B3(DQ0) ; also on sheet 8
H_DDR2_D8: U69.E3(DQ4) ; also on sheet 8
H_DDR2_D9: U69.E7(DQ7) ; also on sheet 8
H_DDR2_D10: U69.E8(DQ5) ; also on sheet 8
H_DDR2_D11: U69.C7(DQ1) ; also on sheet 8
H_DDR2_D12: U69.C8(DQ3) ; also on sheet 8
H_DDR2_D13: U69.B3(DQ0) ; also on sheet 8
H_DDR2_D14: U69.C2(DQ2) ; also on sheet 8
H_DDR2_D15: U69.D2(DQ6) ; also on sheet 8
H_DDR2_D16: U116.C7(DQ1) ; also on sheet 8
H_DDR2_D17: U116.C2(DQ2) ; also on sheet 8
H_DDR2_D18: U116.B3(DQ0) ; also on sheet 8
H_DDR2_D19: U116.C8(DQ3) ; also on sheet 8
H_DDR2_D20: U116.E8(DQ5) ; also on sheet 8
H_DDR2_D21: U116.E7(DQ7) ; also on sheet 8
H_DDR2_D22: U116.E3(DQ4) ; also on sheet 8
H_DDR2_D23: U116.D2(DQ6) ; also on sheet 8
H_DDR2_D24: U68.C7(DQ1) ; also on sheet 8
H_DDR2_D25: U68.E8(DQ5) ; also on sheet 8
H_DDR2_D26: U68.C8(DQ3) ; also on sheet 8
H_DDR2_D27: U68.E3(DQ4) ; also on sheet 8
H_DDR2_D28: U68.E7(DQ7) ; also on sheet 8
H_DDR2_D29: U68.D2(DQ6) ; also on sheet 8
H_DDR2_D30: U68.B3(DQ0) ; also on sheet 8
H_DDR2_D31: U68.C2(DQ2) ; also on sheet 8
H_DDR2_DQM0: U115.B7(DM/TDQS) ; also on sheet 8
H_DDR2_DQM1: U69.B7(DM/TDQS) ; also on sheet 8
H_DDR2_DQM2: U116.B7(DM/TDQS) ; also on sheet 8
H_DDR2_DQM3: U68.B7(DM/TDQS) ; also on sheet 8
H_DDR2_DQS0: U115.C3(DQS) ; also on sheet 8
H_DDR2_DQS1: U69.C3(DQS) ; also on sheet 8
H_DDR2_DQS2: U116.C3(DQS) ; also on sheet 8
H_DDR2_DQS3: U68.C3(DQS) ; also on sheet 8
H_DDR2_DQSN0: U115.D3(~{DQS}) ; also on sheet 8
H_DDR2_DQSN1: U69.D3(~{DQS}) ; also on sheet 8
H_DDR2_DQSN2: U116.D3(~{DQS}) ; also on sheet 8
H_DDR2_DQSN3: U68.D3(~{DQS}) ; also on sheet 8
H_DDR2_ODT0: RN3.2(R2A) TP2MA3.1 TP2MB3.1 U68.G1(ODT) U69.G1(ODT) U115.G1(ODT) U116.G1(ODT) ; also on sheet 8
H_DDR2_RASN: R286.1 TP2MA2.1 TP2MB2.1 U68.F3(~{RAS}) U69.F3(~{RAS}) U115.F3(~{RAS}) U116.F3(~{RAS}) ; also on sheet 8
H_DDR2_RST: U68.N2(~{RESET}) U69.N2(~{RESET}) U115.N2(~{RESET}) U116.N2(~{RESET}) ; also on sheet 8
H_DDR2_WEN: RN3.4(R4A) TP2MA9.1 TP2MB9.1 U68.H3(~{WE}) U69.H3(~{WE}) U115.H3(~{WE}) U116.H3(~{WE}) ; also on sheet 8
H_HDMI_TX0_N: FL7.4
H_HDMI_TX0_P: FL7.1
H_HDMI_TX1_N: FL6.4
H_HDMI_TX1_P: FL6.1
H_HDMI_TX2_N: FL5.4
H_HDMI_TX2_P: FL5.1
H_HDMI_TXC_N: FL8.4
H_HDMI_TXC_P: FL8.1
H_USB1_DM: FL1.4 ; also on sheet 5
H_USB1_DP: FL1.1 ; also on sheet 5
H_USB1_DRV_VBUS: R481.2 U36.4(EN) ; also on sheet 5
H_USB2_DM: FL4.4 ; also on sheet 5
H_USB2_DP: FL4.1 ; also on sheet 5
H_USB2_DRV_VBUS: R532.2 U43.4(EN) ; also on sheet 5
HDMI_CEC_B: P4.13(CE_REMOTE) R517.1 U141.6(CEC_B)
HDMI_CT_HPD: R322.2 U141.11(CT_HPD)
HDMI_DDC_B: P4.16(DDC_DATA) R712.1 U141.8(SDA_B)
HDMI_HPD_A: U141.3(HPD_A)
HDMI_HPD_B: P4.19(HP_DET) R305.1 R713.2 U141.9(HPD_B)
HDMI_LS_OE: R321.2 U141.4(LS_OE)
HDMI_SCL_A: R7.1 U141.1(SCL_A)
HDMI_SCL_B: P4.15(DDC_CLK) R711.1 U141.7(SCL_B)
HDMI_SDA_A: R6.1 U141.2(SDA_A)
HDMI_TX0_N: FL7.3 P4.9(D0-) U138.2(GND)
HDMI_TX0_P: FL7.2 P4.7(D0+) U137.2(GND)
HDMI_TX1_N: FL6.3 P4.6(D1-) U136.2(GND)
HDMI_TX1_P: FL6.2 P4.4(D1+) U135.2(GND)
HDMI_TX2_N: FL5.3 P4.3(D2-) U134.2(GND)
HDMI_TX2_P: FL5.2 P4.1(D2+) U133.2(GND)
HDMI_TXC_N: FL8.3 P4.12(CK-) U140.2(GND)
HDMI_TXC_P: FL8.2 P4.10(CK+) U139.2(GND)
I2C1_SCL: U50.6(SCL2) ; also on sheet 39 52
I2C1_SDA: U50.5(SDA2) ; also on sheet 39 52
LVL_SHIFT_V: U100.10(OE)
MCA1_ACLKX: U48.4(1A1)
MCA1_AFSX: U48.5(1A2)
MCA1_AXR0: U35.6(A4)
MCA1_AXR1: U48.6(2A1)
MCA7_AXR0: U35.9(A7)
MCA7_AXR1: U41.6(2A1)
MCA7_CLKX: U41.4(1A1)
MCA7_FSX: U41.5(1A2)
MCASP1_ENn: U35.22(OEn) U46.22(OEn) U48.14(2~{OE}) U48.15(1~{OE}) ; also on sheet 45
MMC4_CLK: R587.2 U104.4(B)
MMC4_CMD: R520.2 U100.16(B4)
MMC4_DAT0: R521.2 U100.15(B5)
MMC4_DAT1: R522.2 U100.14(B6)
MMC4_DAT2: R523.2 U100.13(B7)
MMC4_DAT3: R524.2 U100.12(B8)
PCM_CLK: P9.52 U41.13(1B1)
PCM_DIN: P9.56 U41.11(2B1)
PCM_DOUT: P9.58 U35.15(B7)
PCM_FSYNC: P9.54 U41.12(1B2)
PMIC_32K_CLKOUT: R222.1 ; also on sheet 40
SLEEP_CLK: P9.1 R222.2
UART3_CTS: U35.8(A6) ; also on sheet 57
UART3_RTS: U46.9(A7) ; also on sheet 57
UART3_RXD: U35.7(A5) ; also on sheet 57
UART3_TXD: U46.10(A8) ; also on sheet 57
USB1_ID: U73.5(ID)
USB1_VBUS_OCN: R771.1 TP27.1 U36.5(OCn)
USB2_ID: U72.5(ID)
USB2_VBUS_OCN: R770.1 TP39.1 U43.5(OCn)
VEVM_1V8: P9.8 R548.1 R600.1 ; also on sheet 37 38 43
VEVM_3V3: C1.1 C331.1 C344.1 C351.1 C404.1 C446.1 C479.1 R1.2 R6.2 R7.2 R301.2 R302.2 R307.2 R321.1 R322.1 R517.2 R519.1 R520.1 R521.1 R522.1 R523.1 R524.1 R528.1 R581.1 R584.1 R587.1 R603.1 R770.2 R771.2 U35.1(VCCA) U41.1(VCCA) U46.1(VCCA) U46.2(DIR) U48.1(VCCA) U100.19(VCCB) U104.6(VCCB) U141.23(VCCA) ; also on sheet 3 12 13 21 22 37 38 40 41 42 43 44 45 46 48 49 51 52 55 56 57
VEVM_3V6: C503.1 C515.1 P9.5 P9.7 R244.1 U56.9(VOUT1) U56.10(VOUT2)
VEVM_5V0: C230.1 C325.1 C340.1 C546.1 R711.2 R712.2 R713.1 U36.2(IN1) U36.3(IN2) U43.2(IN1) U43.3(IN2) U56.1(IN1) U56.2(IN2) U56.4(BIAS) U56.5(EN) U141.10(VCC5V) ; also on sheet 41 48 49 55
VHDMI_5V0: C3.1 P4.18(+5V) U141.12(5V_OUT)
VLVL_SHIFT_V: C332.1 C335.1 C345.1 C405.1 C411.1 C447.1 C448.1 C472.1 R548.2 R558.1 R559.1 R560.1 R561.1 R562.1 U35.23(VCCB) U35.24(VCCB) U41.16(VCCB) U46.23(VCCB) U46.24(VCCB) U48.16(VCCB) U100.2(VCCA) U104.1(VCCA)
VTT_DDR: C164.1 C165.1 C166.1 C167.1 C175.1 C176.1 C180.1 C181.1 C206.1 C207.1 C208.1 C209.1 C626.1 C627.1 C634.1 C635.1 C642.1 C643.1 C653.1 C654.1 C660.1 C661.1 C662.1 C663.1 R286.2 R689.2 RN2.5(R4B) RN2.6(R3B) RN2.7(R2B) RN2.8(R1B) RN3.5(R4B) RN3.6(R3B) RN3.7(R2B) RN3.8(R1B) RN4.5(R4B) RN4.6(R3B) RN4.7(R2B) RN4.8(R1B) RN5.5(R4B) RN5.6(R3B) RN5.7(R2B) RN5.8(R1B) RN6.5(R4B) RN6.6(R3B) RN6.7(R2B) RN6.8(R1B) RN7.5(R4B) RN7.6(R3B) RN7.7(R2B) RN7.8(R1B) RN12.5(R4B) RN12.6(R3B) RN12.7(R2B) RN12.8(R1B) RN13.5(R4B) RN13.6(R3B) RN13.7(R2B) RN13.8(R1B) RN14.5(R4B) RN14.6(R3B) RN14.7(R2B) RN14.8(R1B) RN15.5(R4B) RN15.6(R3B) RN15.7(R2B) RN15.8(R1B) RN16.5(R4B) RN16.6(R3B) RN16.7(R2B) RN16.8(R1B) RN17.5(R4B) RN17.6(R3B) RN17.7(R2B) RN17.8(R1B) ; also on sheet 50
WL_EN: P9.4 U46.19(B3)
WLAN_IRQ: P9.34 U35.21(B1)
ZQ_DBYTE1: R694.1 U115.H8(ZQ)
ZQ_DBYTE2: R289.1 U69.H8(ZQ)
ZQ_DBYTE3: R695.1 U116.H8(ZQ)
ZQ_DBYTE4: R288.1 U68.H8(ZQ)
N16995143: R593.1 R597.1 R600.2 U50.2(VREF1)
N17024050: R178.1 R528.2 U41.2(1DIR)
N17024419: R157.1 R519.2 U41.3(2DIR)
N17038912: R200.1 R584.2 U48.2(1DIR)
N17039180: R196.1 R581.2 U48.3(2DIR)
N17041540: R715.1 U35.14(B8) U35.20(B2)
N17041657: R714.2 U46.3(A1) U46.7(A5) U46.8(A6)
N19184134: P9.12 TP49.1(TP)
N19184365: P9.14 TP46.1(TP)
N19184698: P9.16 TP44.1(TP)
N19185088: P9.73 TP23.1(TP)
N20019184: C601.1 R685.2 R688.2
N21262314: TP1.1 U72.1(VBUS_OUT.1) U72.2(VBUS_OUT.2)
N21262497: R302.1 U72.3(ENn)
N21262499: R307.1 U72.4(ACKn)
N22208304: P9.76 TP22.1(TP)
N22224993: P9.11 TP48.1(TP)
N22225609: P9.13 TP47.1(TP)
N22227190: P9.15 TP45.1(TP)
N24036072: C599.1 R684.2 R687.2
N25164864: C532.1 U56.7(SS)
N25164868: C515.2 R241.1 R244.2 U56.8(FB)
N25214719: R603.2 U50.7(VREF2) U50.8(EN)
N27840356: R301.1 U73.4(ACKn)
N27843210: R1.1 U73.3(ENn)
N28338968: R515.1 U41.14(2~{OE}) U41.15(1~{OE})
N32582765: TP2.1 U73.1(VBUS_OUT.1) U73.2(VBUS_OUT.2)

Not connected (* = marked no-connect by the designer): P4 14(NC.14)*; P9 10* 17* 21* 23* 25* 27* 29* 35* 36* 38* 39* 40* 41* 43* 44* 45* 46* 57* 59* 61* 62* 65* 67* 69* 71* 74* 75* 78* 79* 80* 81* 82* 84* 85* 86* 88* 90* 91* 93* 94* 96* 98* 99* 100*; U35 4(A2) 10(A8); U41 10(2B2); U46 16(B6) 17(B5) 21(B1); U48 10(2B2); U56 3(PG); U68 A3(NC.1)* A7(~{TDQS})* F1(NC.2)* F9(NC.3)* H1(NC.4)* H9(NC.5)*; U69 A3(NC.1)* A7(~{TDQS})* F1(NC.2)* F9(NC.3)* H1(NC.4)* H9(NC.5)*; U100 1(A1) 3(A2) 4(A3); U115 A3(NC.1)* A7(~{TDQS})* F1(NC.2)* F9(NC.3)* H1(NC.4)* H9(NC.5)*; U116 A3(NC.1)* A7(~{TDQS})* F1(NC.2)* F9(NC.3)* H1(NC.4)* H9(NC.5)*; U141 14(CLK-) 15(CLK+) 16(D0-) 17(D0+) 19(D1-) 20(D1+) 21(D2-) 22(D2+)

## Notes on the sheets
sheet 25
- TI CONFIDENTIAL - NDA RESTRICTIONS
- Auto Cap Sizes Updated
- Work - In - Progress
- CAPACITANCE      Commerical     Automotive
  Vaule            Size/X5R       Size/X7R
  .1uF             0201           0402
  .22uF            0201           0603
  .47uF            0201           0603
  1uF              0201           0603
  2.2uF            0402           0603
  4.7uF            0402           0805
  10uF             0402           0805
  22uF             0603           1206
- Preliminary Information - Subject to change
sheet 26
- TI CONFIDENTIAL - NDA RESTRICTIONS
- Auto Cap Sizes Updated
- Work - In - Progress
- CAPACITANCE      Commerical     Automotive
  Vaule            Size/X5R       Size/X7R
  .1uF             0201           0402
  .22uF            0201           0603
  .47uF            0201           0603
  1uF              0201           0603
  2.2uF            0402           0603
  4.7uF            0402           0805
  10uF             0402           0805
  22uF             0603           1206
- Preliminary Information - Subject to change
sheet 27
- TI CONFIDENTIAL - NDA RESTRICTIONS
- MEMORY 3
- MEMORY 1
- MEMORY 4
- MEMORY 2
- This section is an outline of vias labeled as Testpoints
  in the schematic. This allows us to determine pwb line
  lengths for memory to memory and CPU to memory it is
  purely a visibility tool no actual "component" is used
  the vias are just replaced with a via that is  labeled a
  test point
- Work - In - Progress
- Preliminary Information - Subject to change
sheet 28
- Auto Cap Sizes Updated
- TI CONFIDENTIAL - NDA RESTRICTIONS
- Work - In - Progress
- CAPACITANCE      Commerical     Automotive
  Vaule            Size/X5R       Size/X7R
  .1uF             0201           0402
  .22uF            0201           0603
  .47uF            0201           0603
  1uF              0201           0603
  2.2uF            0402           0603
  4.7uF            0402           0805
  10uF             0402           0805
  22uF             0603           1206
- Preliminary Information - Subject to change
sheet 29
- TI CONFIDENTIAL - NDA RESTRICTIONS
- Auto Cap Sizes Updated
- Work - In - Progress
- CAPACITANCE      Commerical     Automotive
  Vaule            Size/X5R       Size/X7R
  .1uF             0201           0402
  .22uF            0201           0603
  .47uF            0201           0603
  1uF              0201           0603
  2.2uF            0402           0603
  4.7uF            0402           0805
  10uF             0402           0805
  22uF             0603           1206
- Preliminary Information - Subject to change
sheet 30
- TI CONFIDENTIAL - NDA RESTRICTIONS
- Auto Cap Sizes Updated
- Work - In - Progress
- CAPACITANCE      Commerical     Automotive
  Vaule            Size/X5R       Size/X7R
  .1uF             0201           0402
  .22uF            0201           0603
  .47uF            0201           0603
  1uF              0201           0603
  2.2uF            0402           0603
  4.7uF            0402           0805
  10uF             0402           0805
  22uF             0603           1206
- Preliminary Information - Subject to change
sheet 31
- TI CONFIDENTIAL - NDA RESTRICTIONS
- DIFFERENTIAL PAIR
  100 OHM DIFFERENTIAL
  IMPEDANCE
  SHORT AND STRAIGHT AS
  POSSIBLE,
  MINIMUM NUMBER OF VIAS
- DIFFERENTIAL PAIR
  100 OHM DIFFERENTIAL
  IMPEDANCE
  SHORT AND STRAIGHT AS
  POSSIBLE,
  MINIMUM NUMBER OF VIAS
- Work - In - Progress
- Preliminary Information - Subject to change
sheet 32
- TI CONFIDENTIAL - NDA RESTRICTIONS
- Work - In - Progress
- Preliminary Information - Subject to change
sheet 33
- TI CONFIDENTIAL - NDA RESTRICTIONS
- Work - In - Progress
- Preliminary Information - Subject to change
sheet 34
- DIR=H : A to B
  DIR=L : B to A
- TI CONFIDENTIAL - NDA RESTRICTIONS
- L = B TO A
  H = A TO B
- Work - In - Progress
- L = B TO A
  H = A TO B
- L = B TO A
  H = A TO B
- Preliminary Information - Subject to change
sheet 35
- TI CONFIDENTIAL - NDA RESTRICTIONS
- Work - In - Progress
- Preliminary Information - Subject to change
sheet 36
- TI CONFIDENTIAL - NDA RESTRICTIONS
- Work - In - Progress
- VOUT = 0.8 * ( 1+(RTOP/RBOTTOM) )
- 3.6 = 0.8 * ( 1+(RTOP/RBOTTOM ))
- 4.5 = ( 1+(RTOP/RBOTTOM ))
- 3.5 = ((RTOP/RBOTTOM ))
- 3.5 RBOTTOM = RTOP
- Preliminary Information - Subject to change
